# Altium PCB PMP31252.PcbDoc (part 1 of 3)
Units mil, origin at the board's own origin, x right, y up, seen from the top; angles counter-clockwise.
Board outline 4527.56 x 3188.98 mil, 6 copper layers (Top Layer, Layer 1, Layer 3, Layer 4, Layer 2, Bottom Layer), stack 32.112 mil thick; 215 components, 83 nets, 499 pads, 1248 vias.
Unrouted connection lines stored in the file: 2.
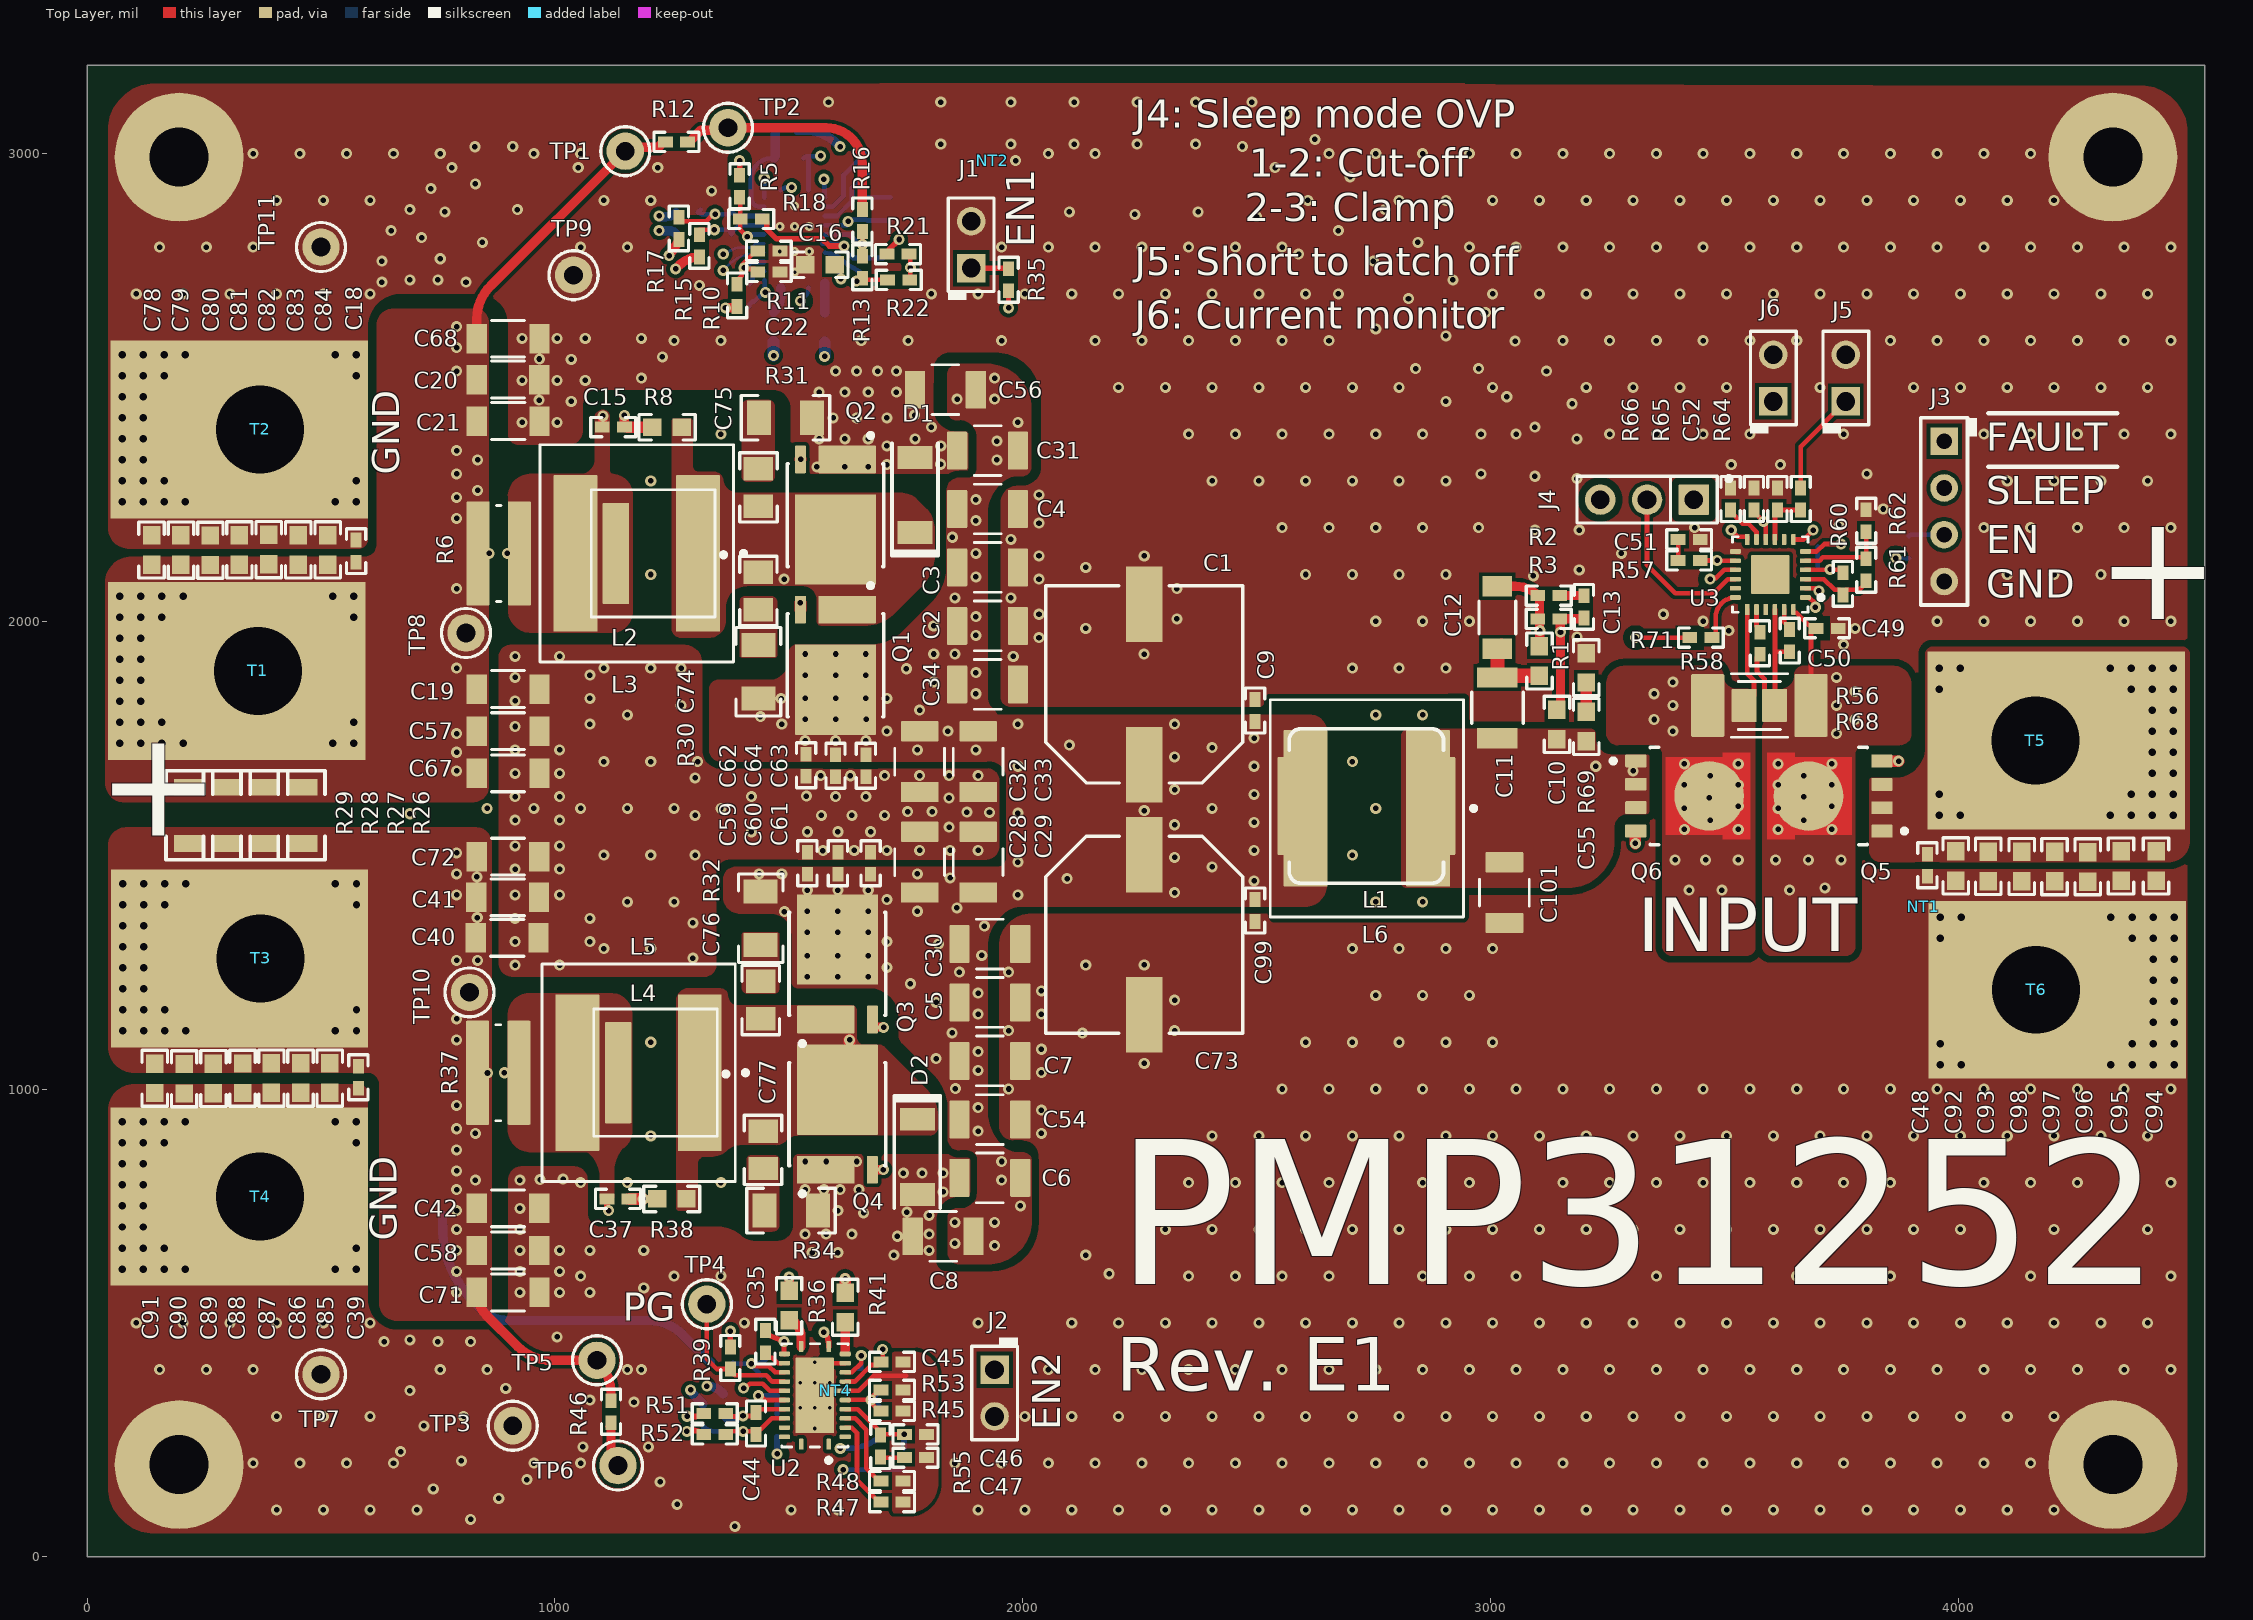
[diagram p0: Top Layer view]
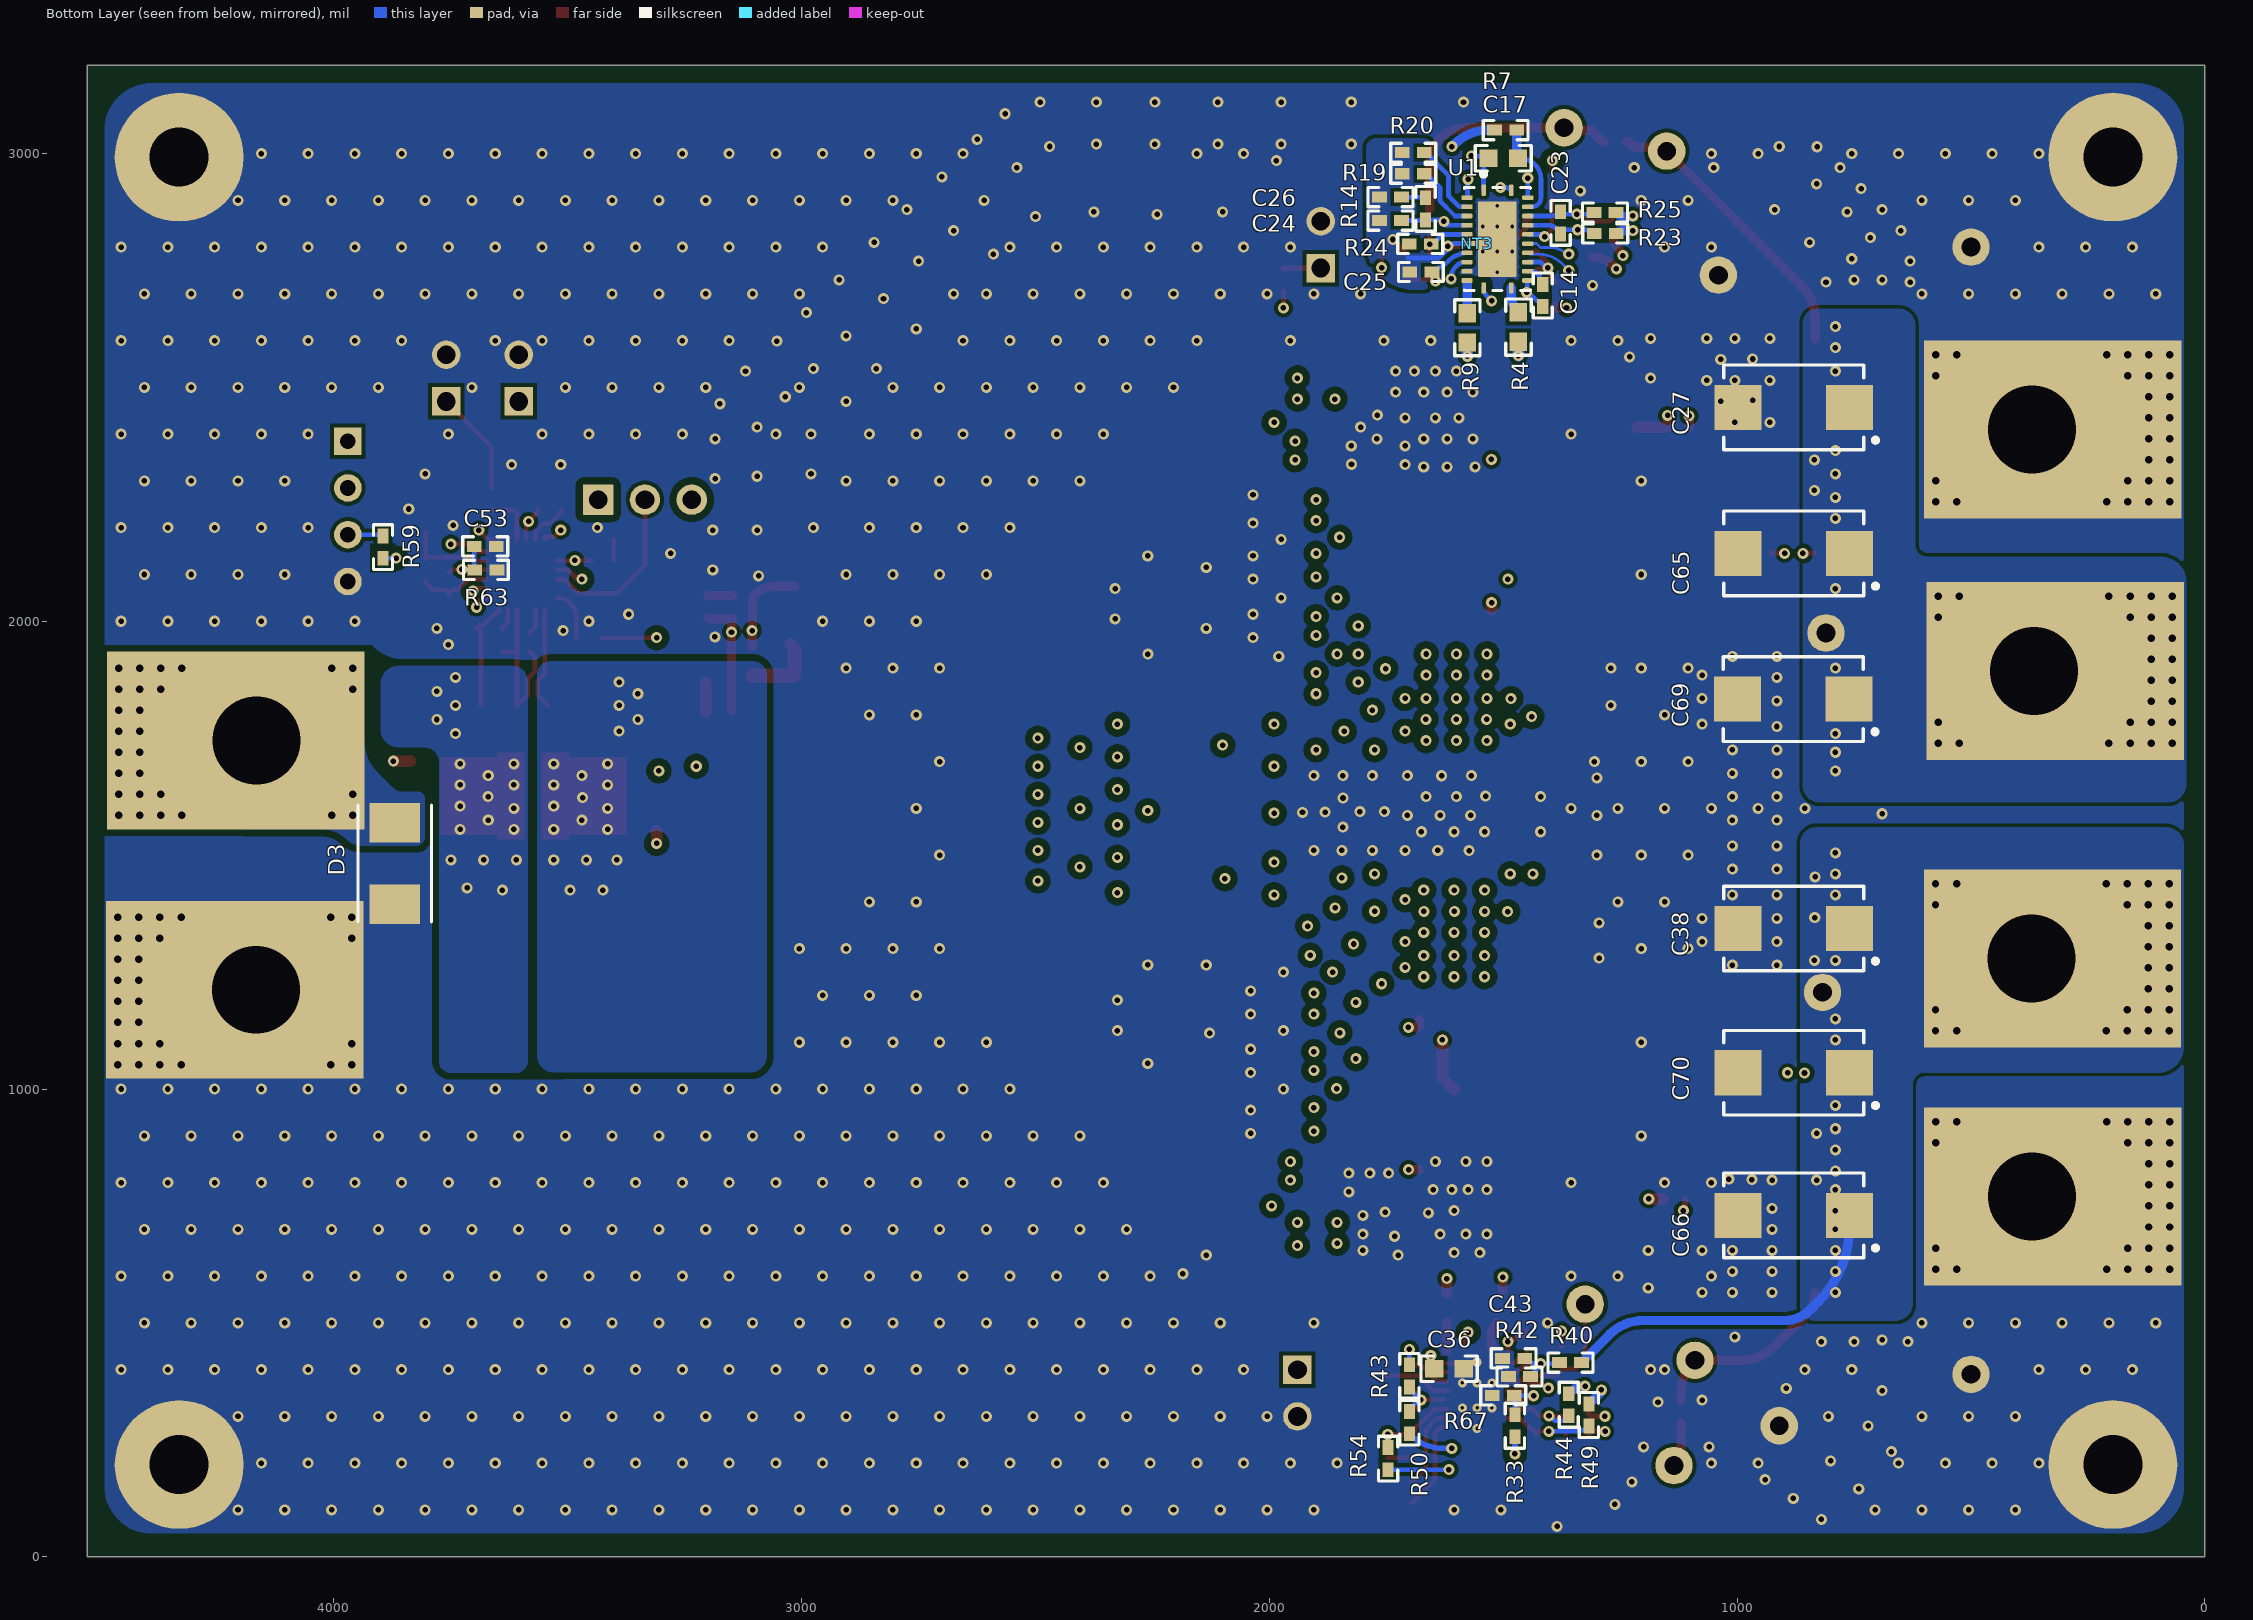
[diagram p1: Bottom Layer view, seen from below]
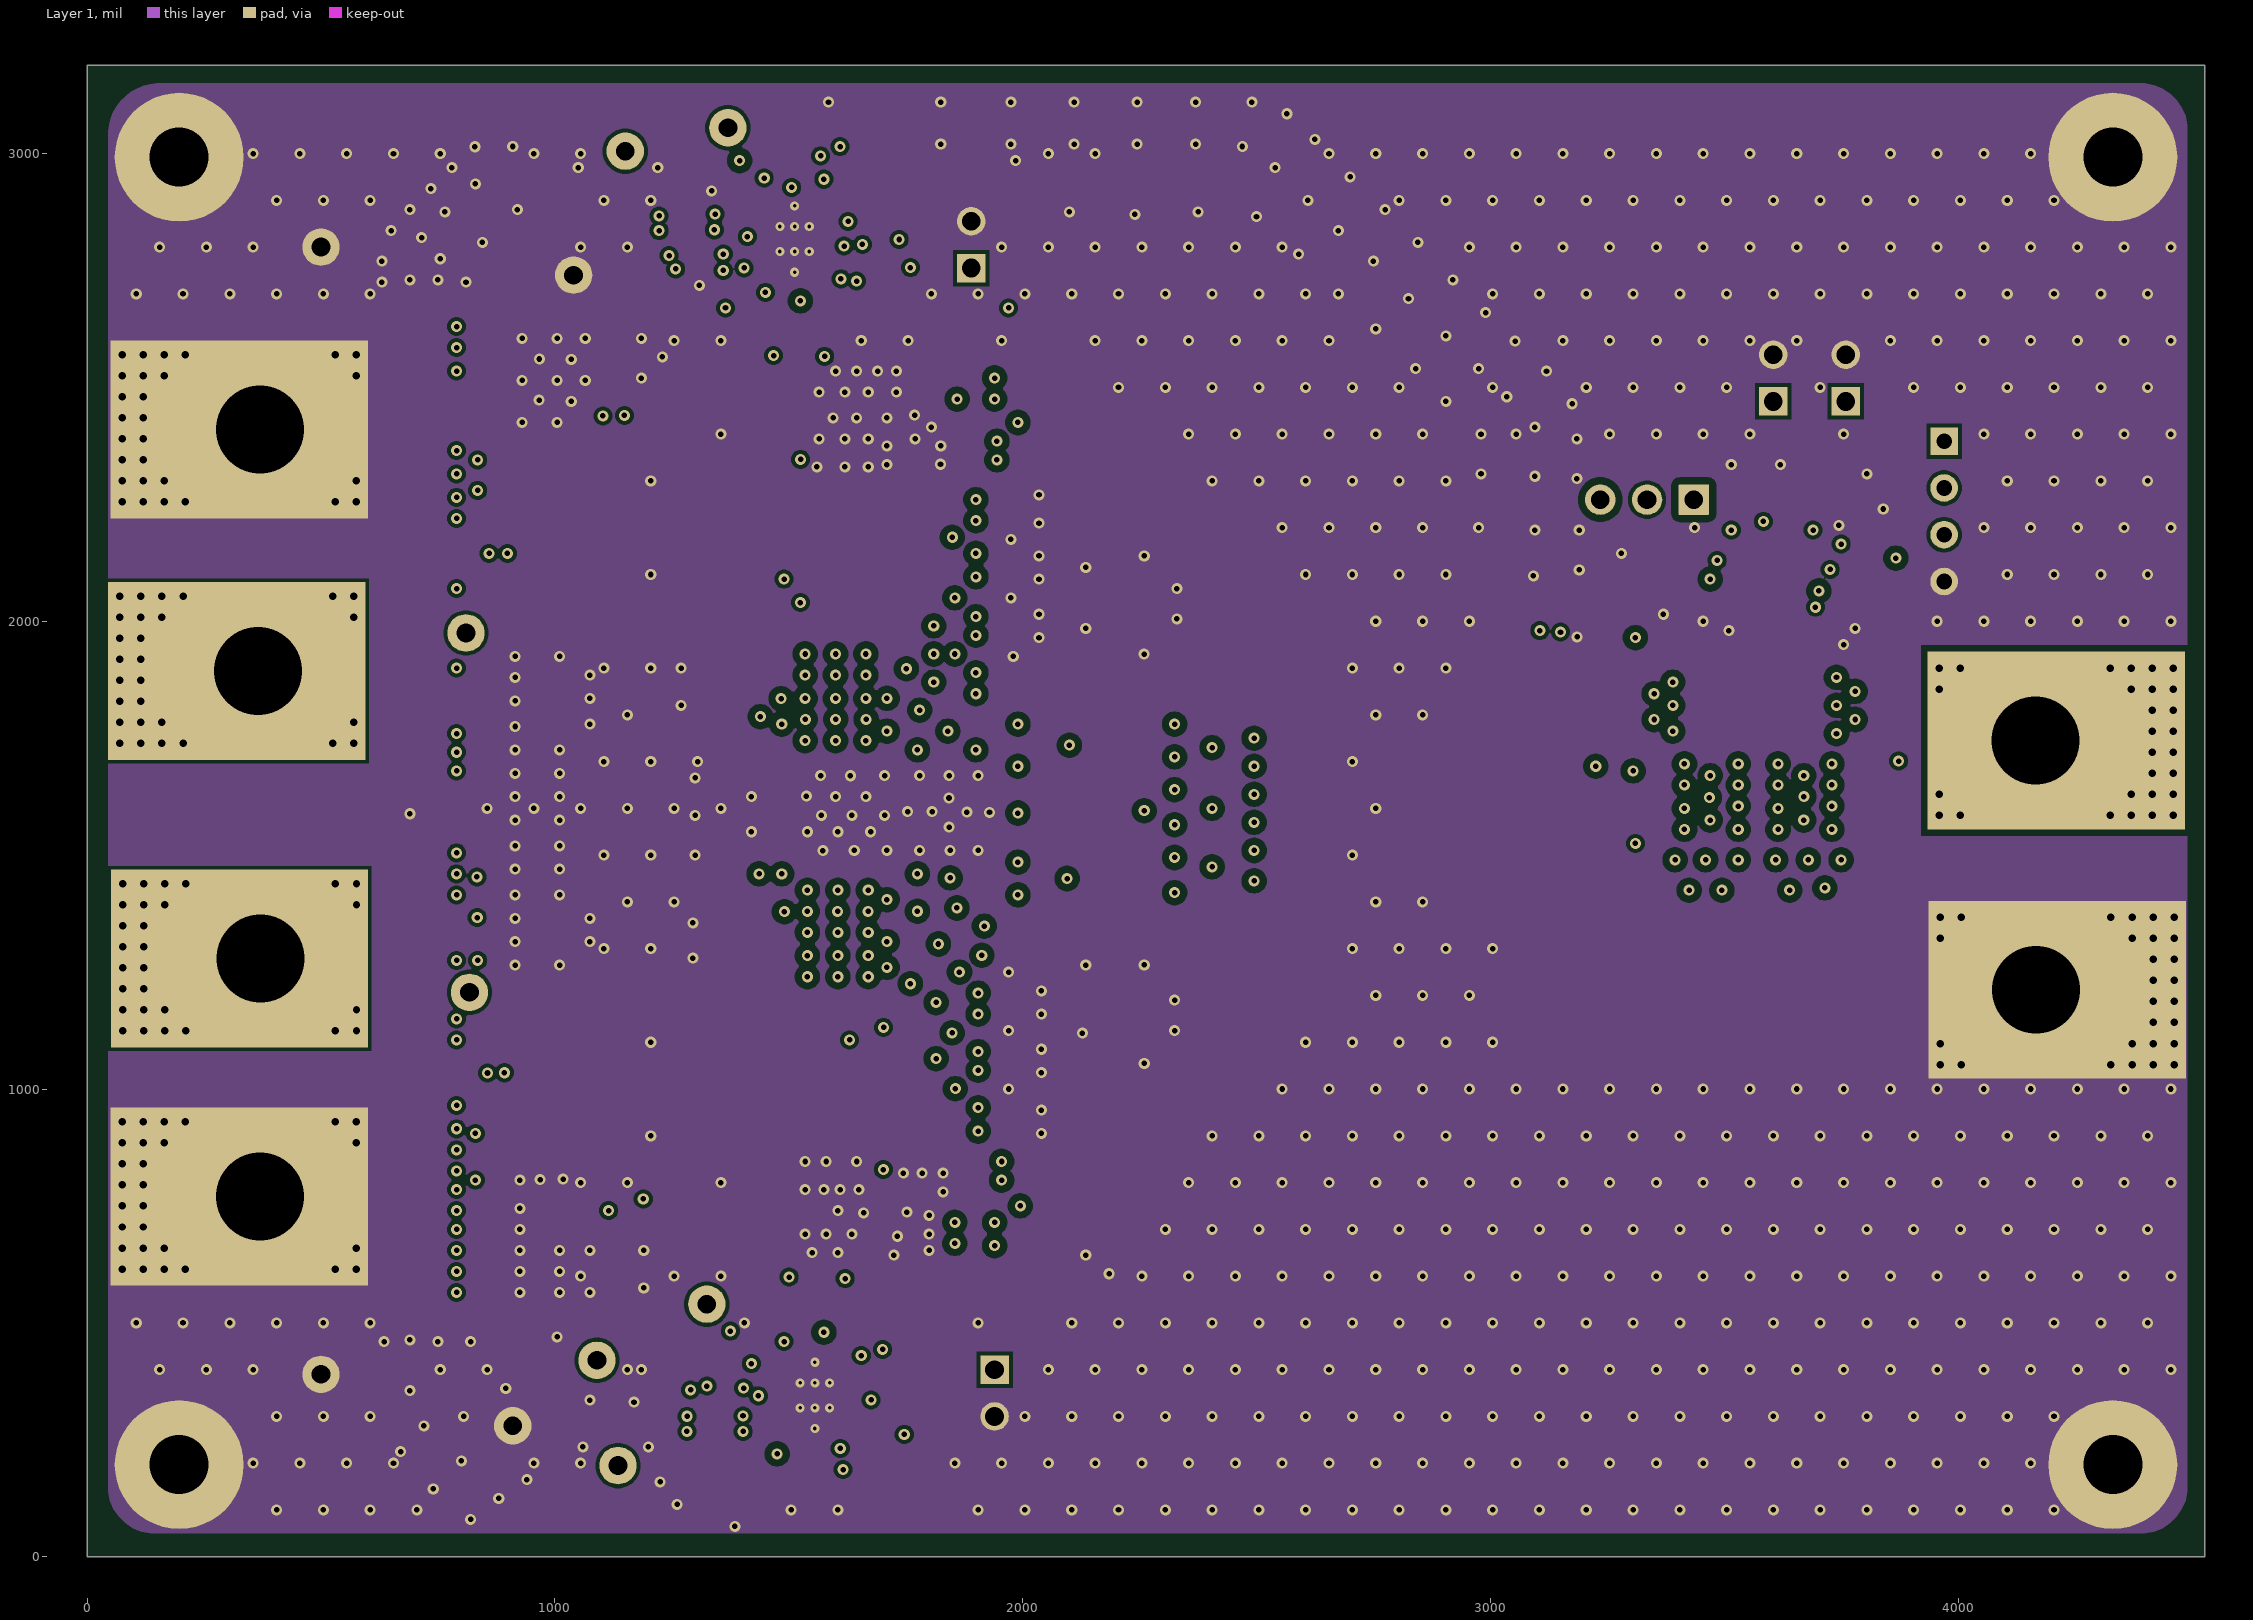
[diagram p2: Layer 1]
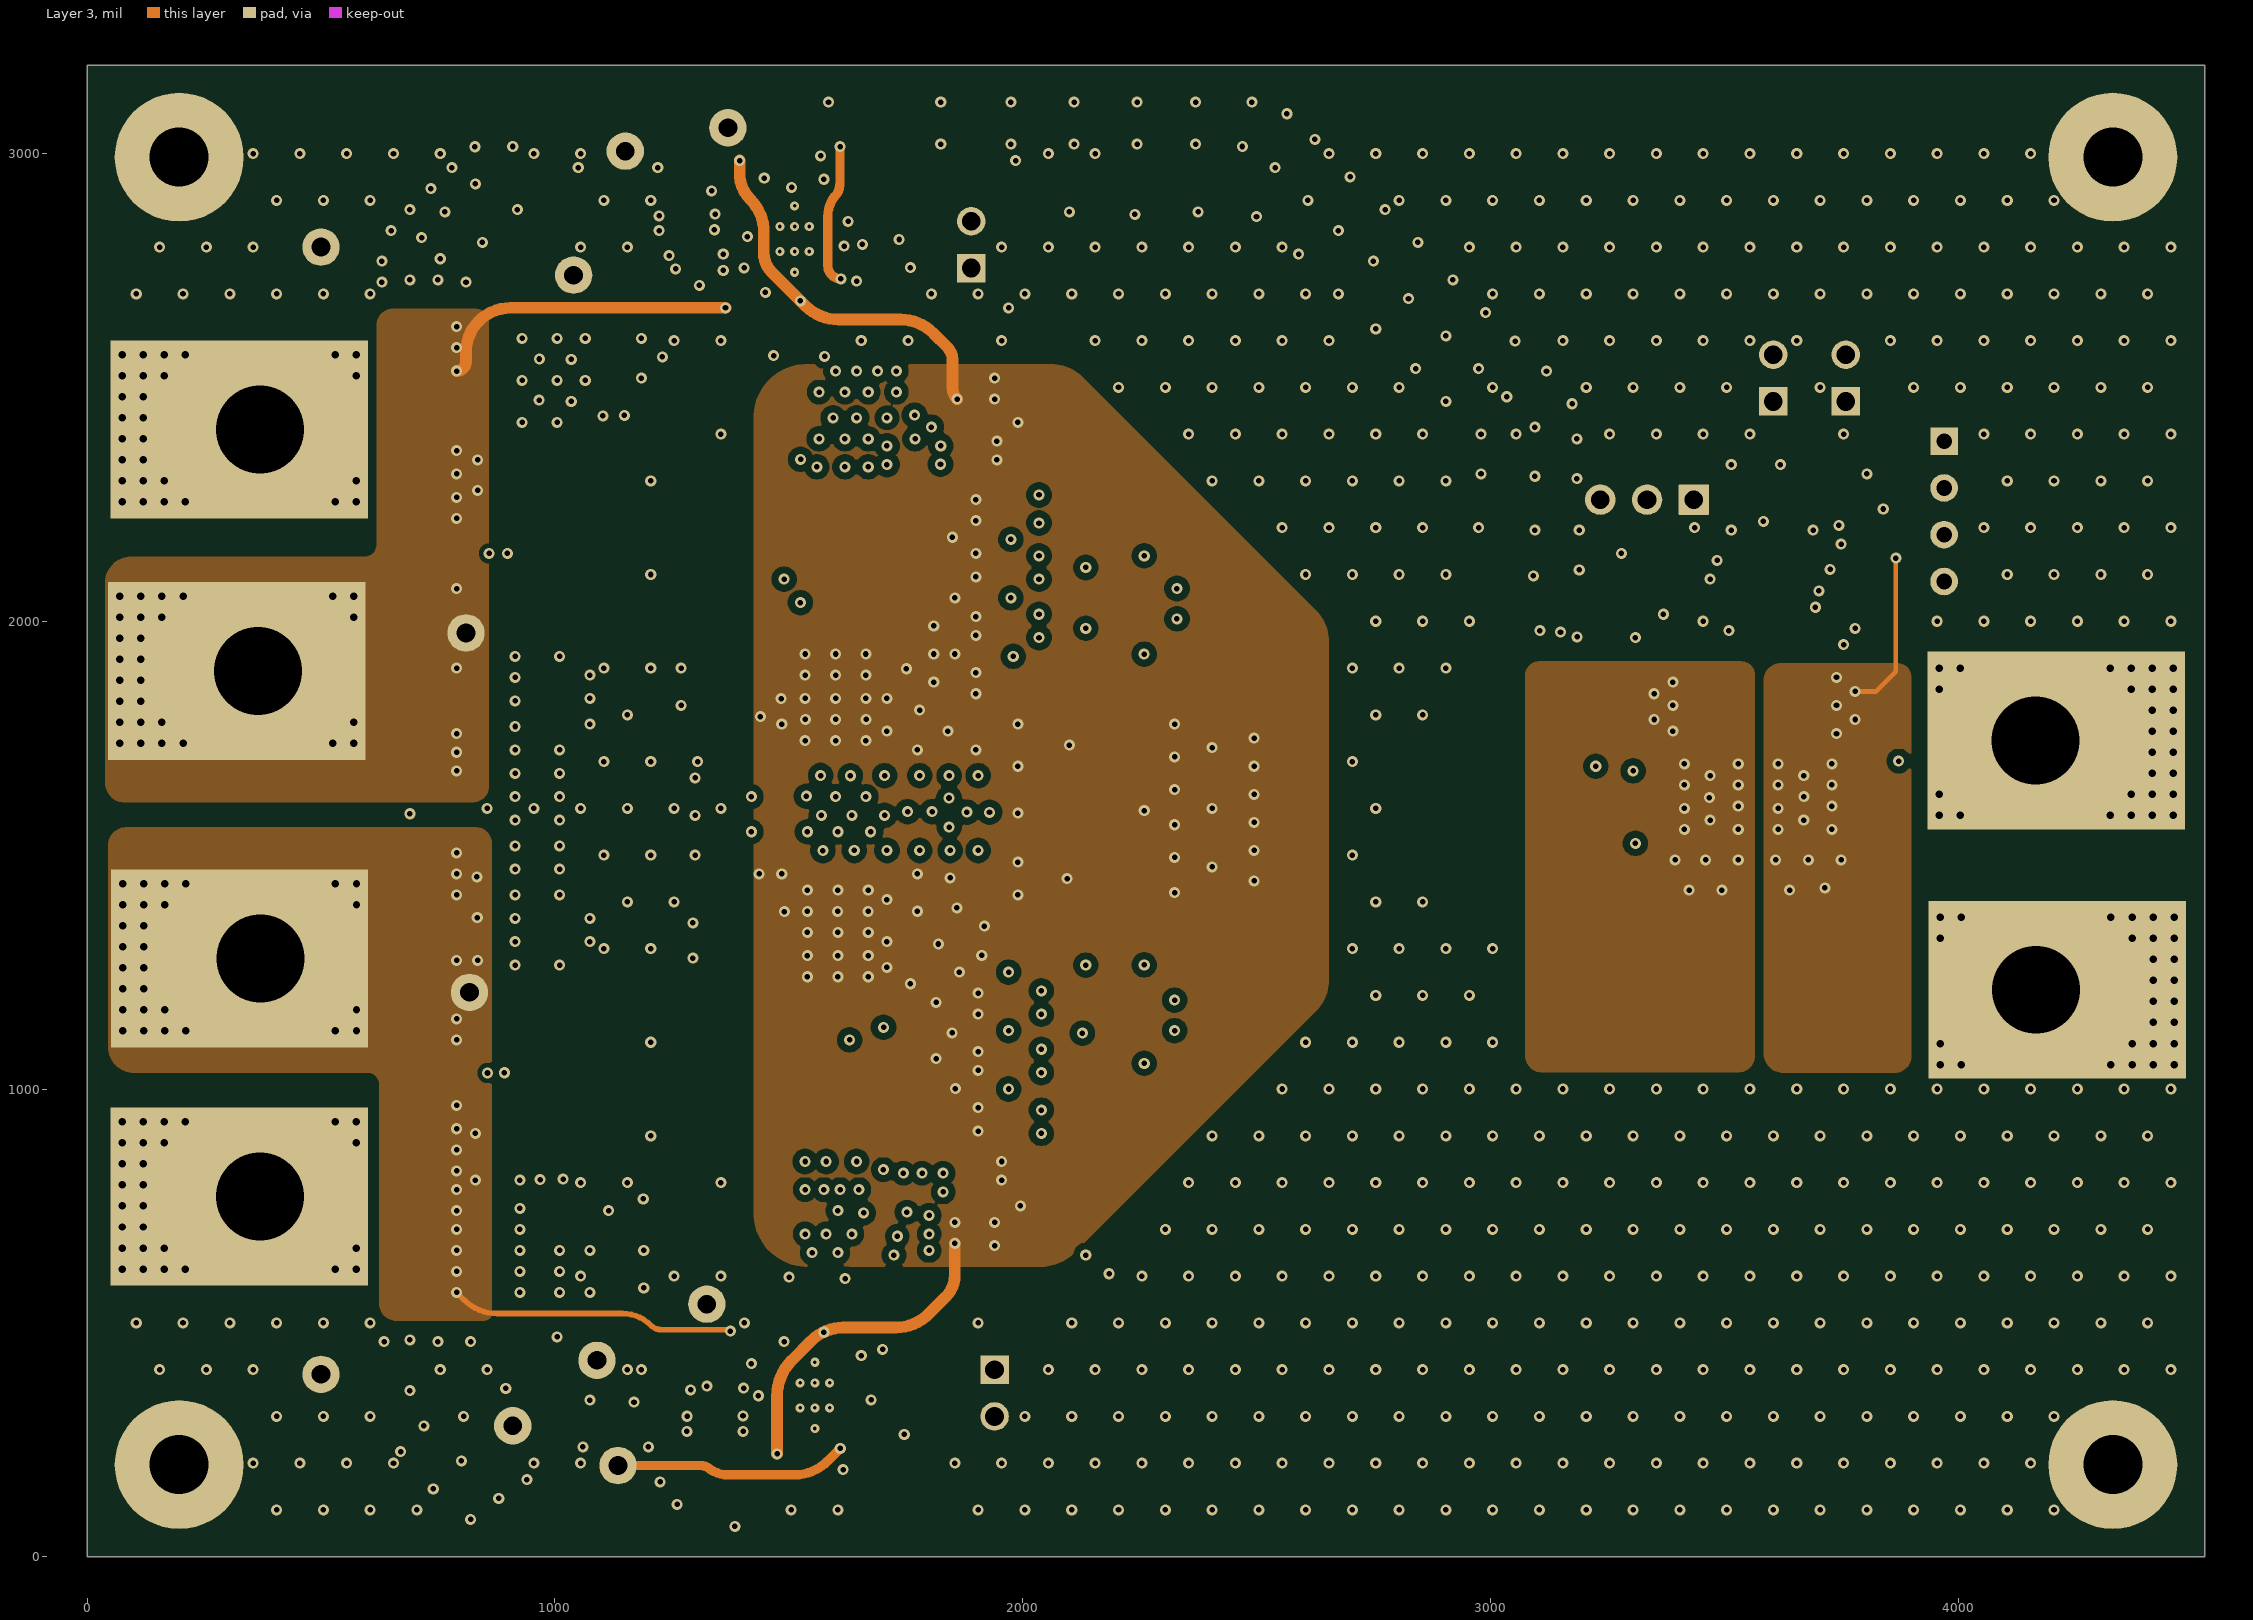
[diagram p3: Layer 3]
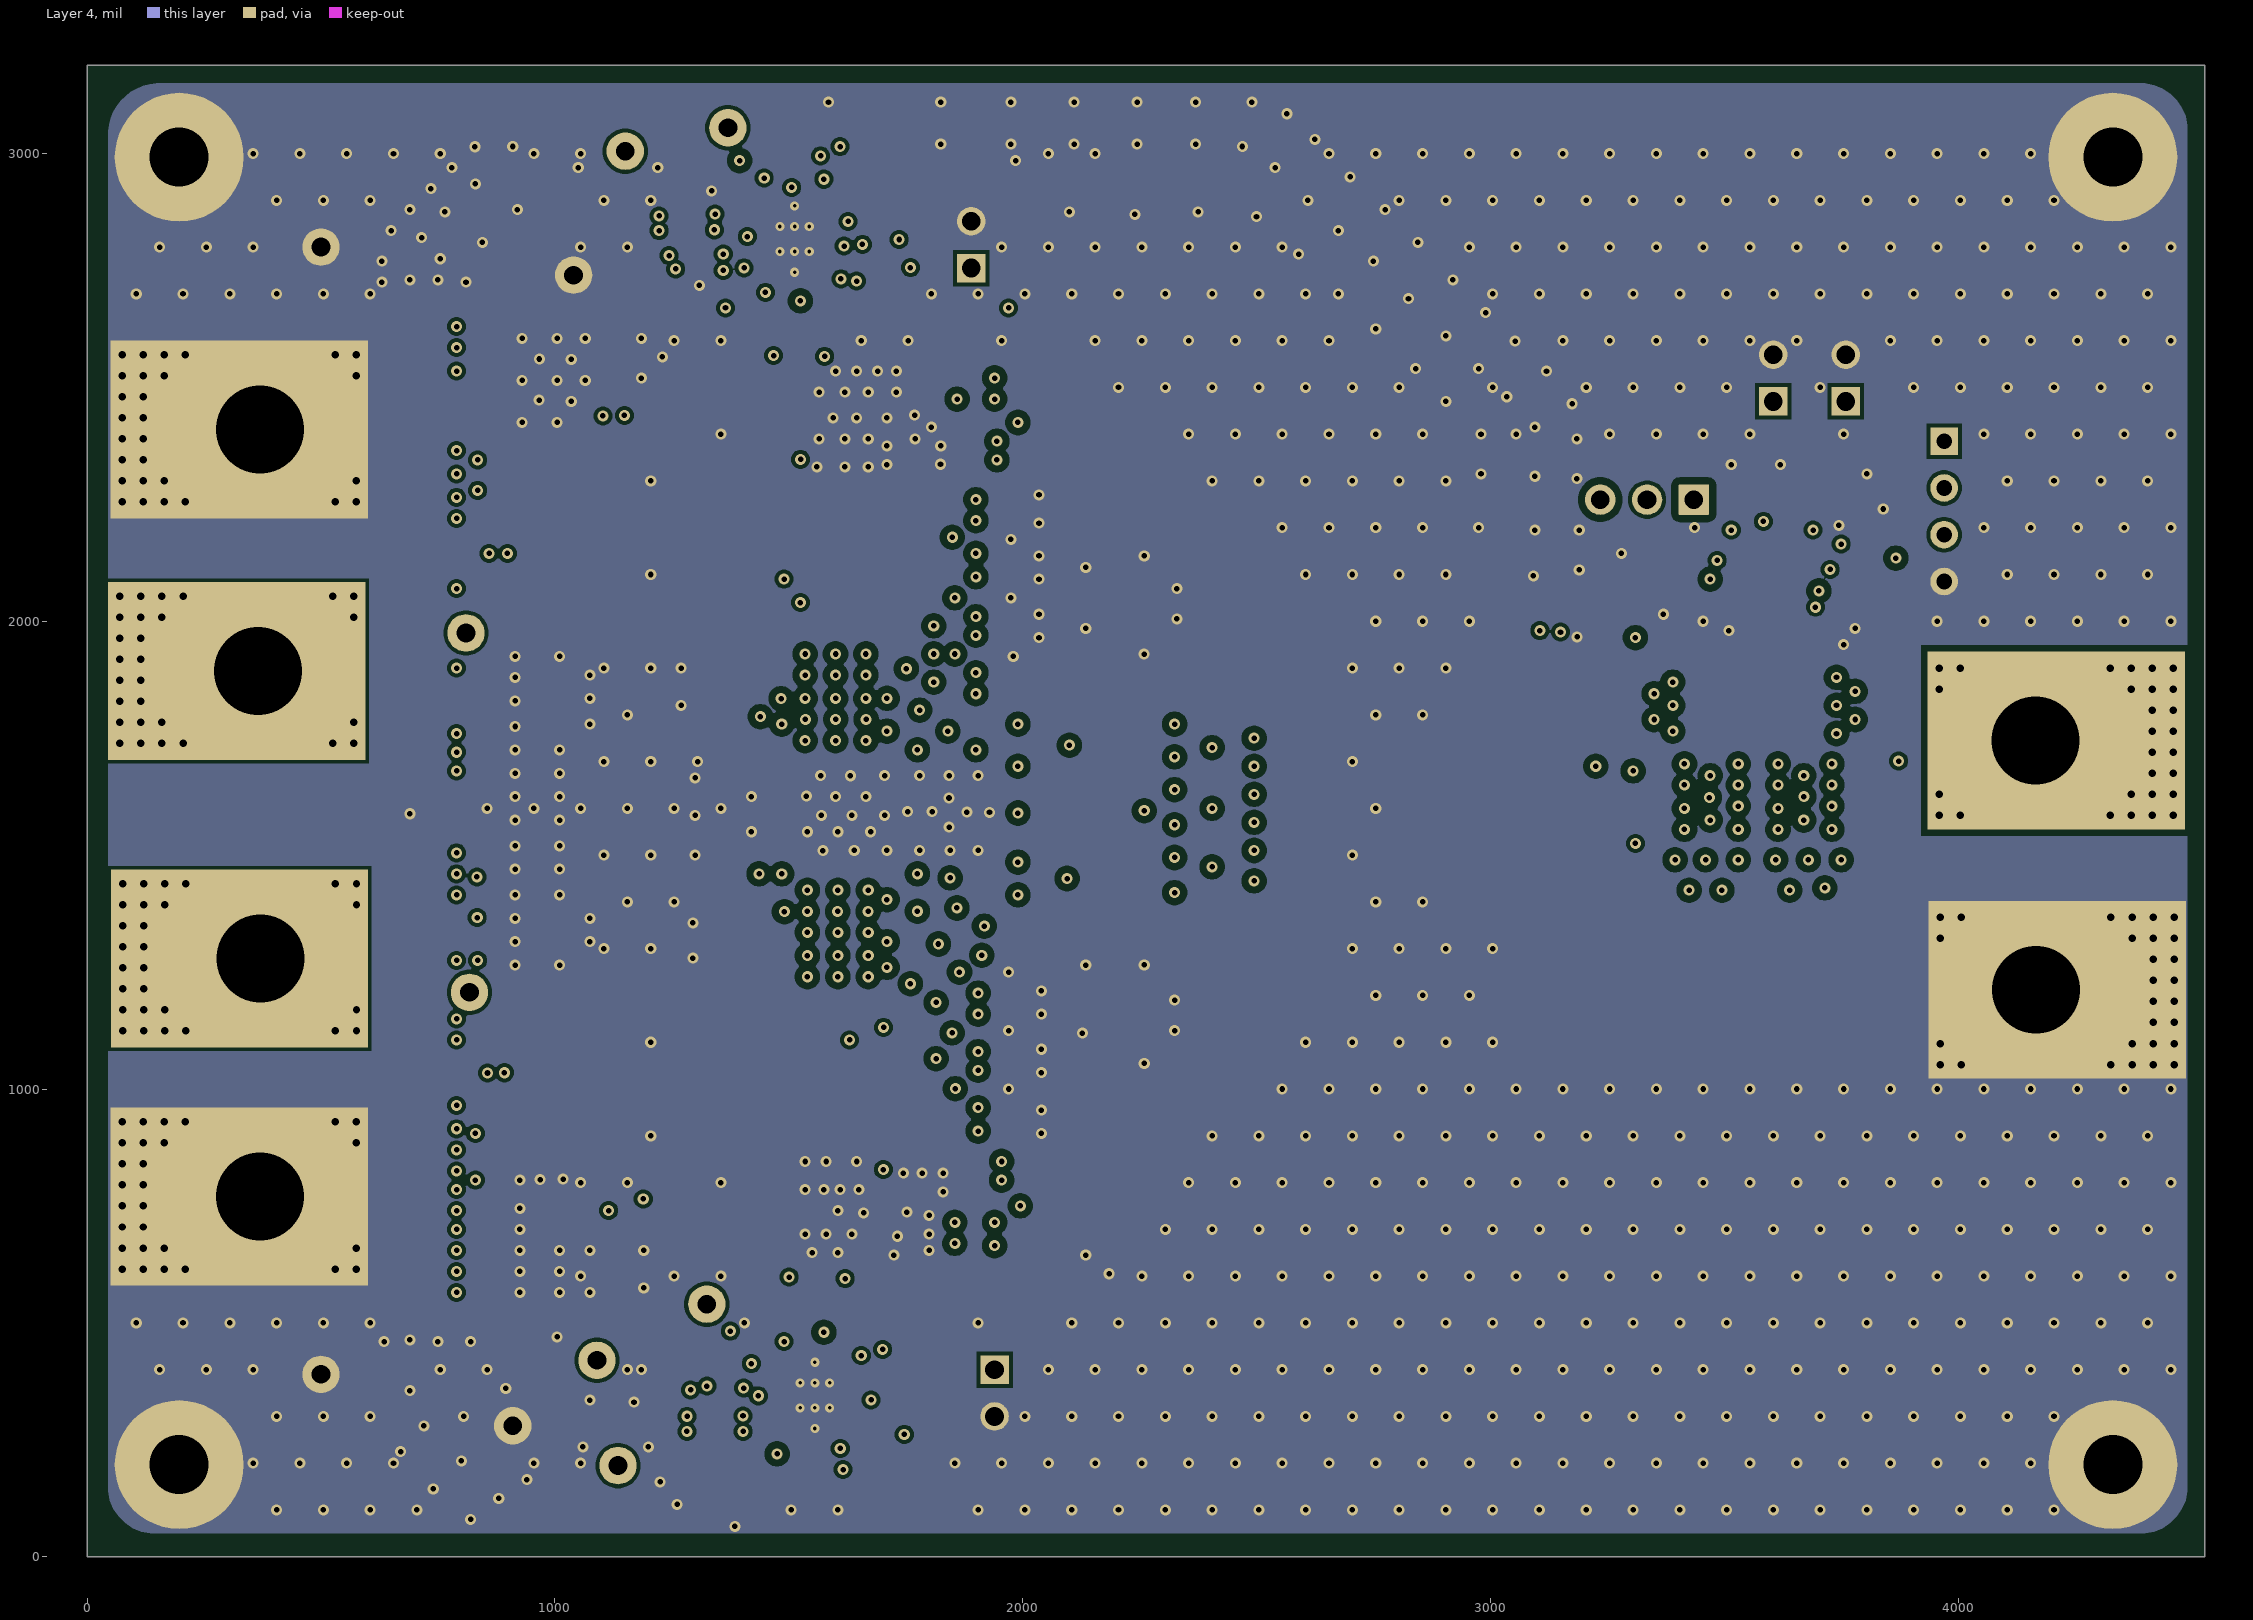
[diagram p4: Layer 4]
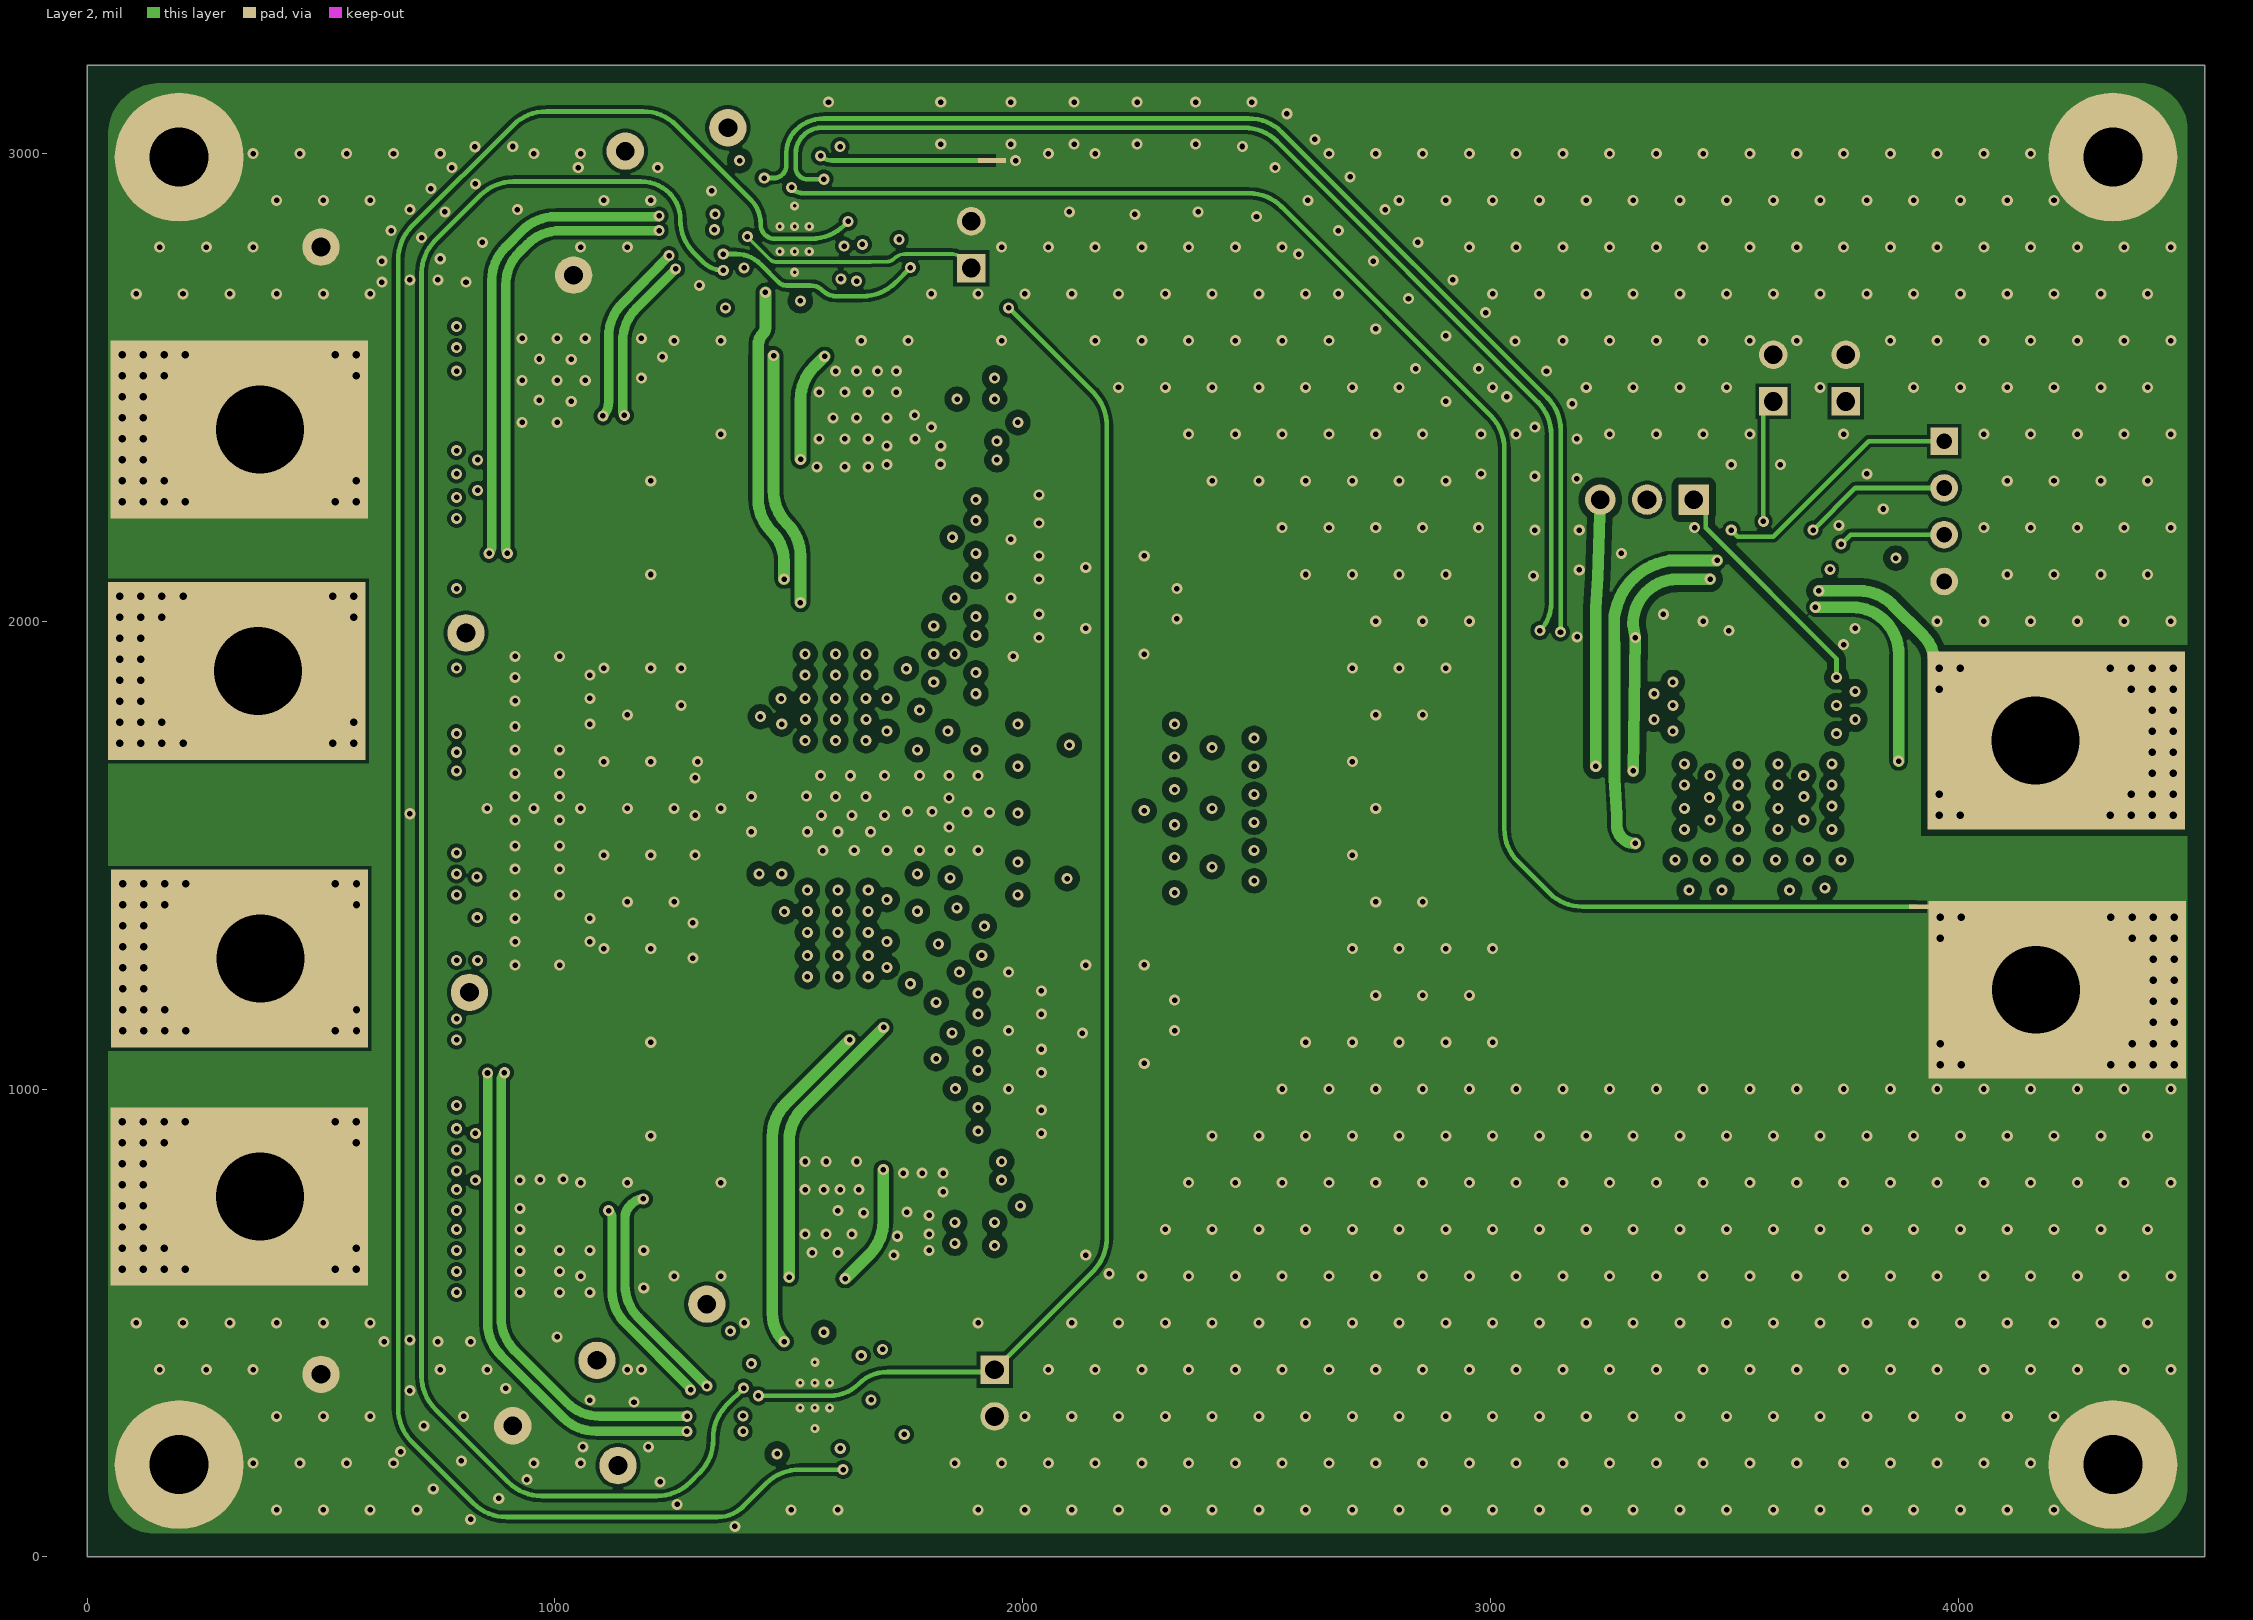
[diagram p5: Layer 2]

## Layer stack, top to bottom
Top Solder: solder mask 0.4, Solder Resist, Dk 3.5
Top Layer: signal copper 1.4
Dielectric 2: prepreg 2.8, PP-006, Dk 4.1
Layer 1: signal copper 1.378
Dielectric 4: prepreg 2.8, PP-006, Dk 4.1
Layer 3: signal copper 1.378
Dielectric 1: dielectric 12.6, FR-4, Dk 4.8
Layer 4: signal copper 1.378
Dielectric 5: prepreg 2.8, PP-006, Dk 4.1
Layer 2: signal copper 1.378
Dielectric 3: prepreg 2.8, PP-006, Dk 4.1
Bottom Layer: signal copper 1.4
Bottom Solder: solder mask 0.4, Solder Resist, Dk 3.5

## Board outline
0,0 0,3188.98 4527.56,3188.98 4527.56,0

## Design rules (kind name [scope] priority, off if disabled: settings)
Clearance Vin [InNet('Vin_FLT') OR InNet('VIN_PROT') OR InNet('NetC48_1') OR InNet('NetC49_1') OR InNet('NetQ6_5')] p1: gap=15 ignorepadtopadclearanceinfootprint=FALSE
Clearance Clearance_1 [All] p2: gap=8 ignorepadtopadclearanceinfootprint=FALSE
MinimumSolderMaskSliver [All] p1: minsoldermaskwidth=5
PolygonConnect [All] p1: connectstyle=Direct reliefconductorwidth=10 reliefentries=4 polygonreliefangle="90 Angle" airgapwidth=10
RoutingVias [All] p1: holewidth=11.81 width=23.62 viastyle="Through Hole" minholewidth=11.81 minwidth=23.62 maxholewidth=28 maxwidth=50
SilkToSolderMaskClearance [IsPad] p1: minsilkscreentomaskgap=5 clearancetoexposedcopper=TRUE
SolderMaskExpansion [All] p1: expansion=4 istentingtop=FALSE
Width [All] p1: maxlimit=50 minlimit=5 preferedwidth=10 minimp=50.000000 maximp=50.000000 favimp=50.000000
28 further rules are at their usual default settings.

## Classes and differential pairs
component class PMP31252RevA_S: C28 C29 C30 C31 C32 C33 C34 C35 C36 C37 C38 C39 C40 C41 C42 C43 C44 C45 C46 C47 C58 C62 C63 C64 C66 C70 C71 C72 C76 C77 C85 C86 C87 C88 C89 C90 C91 D2 L4 L5 NT4 Q3 Q4 R32 R34 R36 R37 R38 R39 R40 R41 R42 R43 R44 R45 R46 R47 R48 R49 R50 R51 R52 R53 R54 R55 T3 T4 TP4 TP5 TP6 TP7 U2
component class PMP31252RevA_M: C1 C2 C3 C4 C5 C6 C7 C8 C9 C10 C11 C12 C13 C14 C15 C16 C17 C18 C19 C20 C21 C22 C23 C24 C25 C26 C27 C54 C55 C56 C57 C59 C60 C61 C65 C67 C68 C69 C73 C74 C75 C78 C79 C80 C81 C82 C83 C84 C99 C101 D1 J1 J2 L1 L2 L3 L6 NT1 NT2 NT3 Q1 Q2 R1 R2 R3 R4 R5 R6 R7 R8 R9 R10 R11 R12 R13 R14 R15 R16 R17 R18 R19 R20 R21 R22 R23 R24 R25 R26 R27 R28 R29 R30 R31 R33 R35 R67 R69 T1 T2 TP1 TP2 TP3 TP8 TP9 TP10 TP11 U1
component class PMP31252RevA_Input: C48 C49 C50 C51 C52 C53 C92 C93 C94 C95 C96 C97 C98 D3 J3 J4 J5 J6 Q5 Q6 R56 R57 R58 R59 R60 R61 R62 R63 R64 R65 R66 R68 R71 T5 T6 U3

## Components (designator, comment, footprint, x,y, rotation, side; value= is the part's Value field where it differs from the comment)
C1 "EEE-FT1H331AP" SM_RADIAL_G 2260,1865 r90 top value=330uF
C2 "GCM32EC71H106KA03L" FP-GCM32EC71H106KA03L_1210-MFG 1925,1990 r180 top value=10µF
C3 "GCM32EC71H106KA03L" FP-GCM32EC71H106KA03L_1210-MFG 1925,2115 r180 top value=10µF
C4 "GCM32EC71H106KA03L" FP-GCM32EC71H106KA03L_1210-MFG 1925,2240 r180 top value=10µF
C5 "GCM32EC71H106KA03L" FP-GCM32EC71H106KA03L_1210-MFG 1930,1185 r180 top value=10µF
C6 "GCM32EC71H106KA03L" FP-GCM32EC71H106KA03L_1210-MFG 1930,810 r0 top value=10µF
C7 "GCM32EC71H106KA03L" FP-GCM32EC71H106KA03L_1210-MFG 1930,1060 r180 top value=10µF
C8 "GCM32EC71H106KA03L" FP-GCM32EC71H106KA03L_1210-MFG 1830,685 r0 top value=10µF
C9 "CGA2B3X8R1H103K050BB" 0402 2497.18,1809.13 r90 top value=0.01uF
C10 "CGA3E3X8R1H104K080AE" 0603 3142.27,1779.54 r90 top value=0.1uF
C11 "CGA6P3X7R1H475K250AB" 1210_280 3015,1815 r90 top value=4.7uF
C12 "GCM31CR71H225KA55L" 1206_180 3014.8,2008.05 r90 top value=2.2uF
C13 "GCM155R71H102KA37D" 0402 3199.93,2030.64 r270 top value=1000pF
C14 "CGA2B3X7R1E104K050BB" 0402 1415.62,2696.54 r90 bottom value=0.1uF
C15 "GCM155R71H104KE02D" 0402 1125,2415 r0 top value=0.1uF
C16 "GRM188R71A225KE15J" 0603 1566.75,2762.44 r180 top value=2.2uF
C17 "GRM188R71A225KE15J" 0603 1500,2990 r0 bottom value=2.2uF
C18 "CGA2B3X7R1E104K050BB" 0402 575,2150 r90 top value=0.1uF
C19 "GCM31CR71A226KE02L" 1206_180 900,1855 r0 top value=22uF
C20 "GCM31CR71A226KE02L" 1206_180 899.76,2516.73 r0 top value=22uF
C21 "GCM31CR71A226KE02L" 1206_180 900.18,2428.08 r0 top value=22uF
C22 "CGA2B3X7R1E104K050BB" 0402 1457.52,2746.69 r0 top value=0.1uF
C23 "CGA2B3X7R1H153K050BB" 0402 1377.52,2851.69 r90 bottom value=0.015uF
C24 "CGA2B2C0G1H151J050BA" 0402 1741.14,2856.69 r0 bottom value=150pF
C25 "CGA2B3X7R1E104K050BB" 0402 1676.14,2746.69 r0 bottom value=0.1uF
C26 "CGA2B3X7R1H153K050BB" 0402 1741.14,2906.69 r0 bottom value=0.015uF
C27 "T598D227M010ATE025" 7343-31 878.98,2457.08 r0 bottom value=220uF
C28 "GCM32EC71H106KA03L" FP-GCM32EC71H106KA03L_1210-MFG 1780,1485 r270 top value=10µF
C29 "GCM32EC71H106KA03L" FP-GCM32EC71H106KA03L_1210-MFG 1905,1485 r270 top value=10µF
C30 "GCM32EC71H106KA03L" FP-GCM32EC71H106KA03L_1210-MFG 1930,1310 r180 top value=10µF
C31 "GCM32EC71H106KA03L" FP-GCM32EC71H106KA03L_1210-MFG 1925,2365 r0 top value=10µF
C32 "GCM32EC71H106KA03L" FP-GCM32EC71H106KA03L_1210-MFG 1780,1700 r90 top value=10µF
C33 "GCM32EC71H106KA03L" FP-GCM32EC71H106KA03L_1210-MFG 1905,1700 r90 top value=10µF
C34 "GCM32EC71H106KA03L" FP-GCM32EC71H106KA03L_1210-MFG 1925,1865 r180 top value=10µF
C35 "CGA2B3X7R1E104K050BB" 0402 1450,460 r270 top value=0.1uF
C36 "GRM188R71A225KE15J" 0603 1615.87,401.77 r0 bottom value=2.2uF
C37 "GCM155R71H104KE02D" 0402 1135,765 r0 top value=0.1uF
C38 "T598D227M010ATE025" 7343-31 879.16,1343.22 r0 bottom value=220uF
C39 "CGA2B3X7R1E104K050BB" 0402 580,1025 r270 top value=0.1uF
C40 "GCM31CR71A226KE02L" 1206_180 897.98,1323.19 r0 top value=22uF
C41 "GCM31CR71A226KE02L" 1206_180 898.99,1409.78 r0 top value=22uF
C42 "GCM31CR71A226KE02L" 1206_180 899.83,744.78 r0 top value=22uF
C43 "CGA2B3X7R1E104K050BB" 0402 1477.83,424.06 r0 bottom value=0.1uF
C44 "CGA2B3X7R1H153K050BB" 0402 1430,285 r270 top value=0.015uF
C45 "CGA2B3X7R1E104K050BB" 0402 1720.87,416.77 r0 top value=0.1uF
C46 "CGA2B2C0G1H151J050BA" 0402 1770.87,261.77 r0 top value=150pF
C47 "CGA2B3X7R1H153K050BB" 0402 1770.87,211.77 r0 top value=0.015uF
C48 "CGA2B3X7R1H104K050BD" 0402 3934.34,1478.53 r270 top value=0.1uF
C49 "CGA2B3X7R1H104K050BD" 0402 3720,1985 r0 top value=0.1uF
C50 "CGA2B3X7R1H104K050BD" 0402 3640,1958.62 r90 top value=0.1uF
C51 "CGA2B3X8R1H103K050BB" 0402 3425,2175 r0 top value=0.01uF
C52 "CGA2B3X8R1H103K050BB" 0402 3613.5,2261.38 r90 top value=0.01uF
C53 "CGA2B3X8R1H103K050BB" 0402 3676.38,2160 r180 bottom value=0.01uF
C54 "GCM32EC71H106KA03L" FP-GCM32EC71H106KA03L_1210-MFG 1930,934.76 r180 top value=10µF
C55 "CGA3E3X8R1H104K080AE" 0603 3205,1775 r90 top value=0.1uF
C56 "GCM32EC71H106KA03L" FP-GCM32EC71H106KA03L_1210-MFG 1835,2495 r0 top value=10µF
C57 "GCM31CR71A226KE02L" 1206_180 900,1765 r0 top value=22uF
C58 "GCM31CR71A226KE02L" 1206_180 899.83,654.78 r0 top value=22uF
C59 "CGA2B3X7R1E104K050BB" 0402 1539.95,1482.66 r90 top value=0.1uF
C60 "CGA2B3X7R1E104K050BB" 0402 1604.95,1482.66 r90 top value=0.1uF
C61 "CGA2B3X7R1E104K050BB" 0402 1674.95,1482.66 r90 top value=0.1uF
C62 "CGA2B3X7R1E104K050BB" 0402 1537.06,1692.06 r270 top value=0.1uF
C63 "CGA2B3X7R1E104K050BB" 0402 1664.96,1690.94 r270 top value=0.1uF
C64 "CGA2B3X7R1E104K050BB" 0402 1599.96,1690.94 r270 top value=0.1uF
C65 "T598D227M010ATE025" 7343-31 878.98,2145 r0 bottom value=220uF
C66 "T598D227M010ATE025" 7343-31 878.98,729.85 r0 bottom value=220uF
C67 "GCM31CR71A226KE02L" 1206_180 900,1675 r0 top value=22uF
C68 "GCM31CR71A226KE02L" 1206_180 899.98,2603.97 r0 top value=22uF
C69 "T598D227M010ATE025" 7343-31 880,1833.65 r0 bottom value=220uF
C70 "T598D227M010ATE025" 7343-31 878.98,1034.78 r0 bottom value=220uF
C71 "GCM31CR71A226KE02L" 1206_180 900,565 r0 top value=22uF
C72 "GCM31CR71A226KE02L" 1206_180 899.68,1496.71 r0 top value=22uF
C73 "EEE-FT1H331AP" SM_RADIAL_G 2260,1330 r270 top value=330uF
C74 "GRM21BR72A103KA01L" 0805_HV 1435,2065 r90 top value=0.01uF
C75 "GRM21BR72A103KA01L" 0805_HV 1435.26,2286.16 r90 top value=0.01uF
C76 "GRM21BR72A103KA01L" 0805_HV 1440,1190 r270 top value=0.01uF
C77 "GRM21BR72A103KA01L" 0805_HV 1445,870 r270 top value=0.01uF
C78 "CGA3E3X8R1H104K080AE" 0603 137.9,2152.29 r90 top value=0.1uF
C79 "CGA3E3X8R1H104K080AE" 0603 200.62,2152 r90 top value=0.1uF
C80 "CGA3E3X8R1H104K080AE" 0603 263.5,2151.8 r90 top value=0.1uF
C81 "CGA3E3X8R1H104K080AE" 0603 325.52,2152.53 r90 top value=0.1uF
C82 "CGA3E3X8R1H104K080AE" 0603 388.27,2153.13 r90 top value=0.1uF
C83 "CGA3E3X8R1H104K080AE" 0603 451.19,2152.68 r90 top value=0.1uF
C84 "CGA3E3X8R1H104K080AE" 0603 514.46,2152.68 r90 top value=0.1uF
C85 "CGA3E3X8R1H104K080AE" 0603 518.72,1023.19 r270 top value=0.1uF
C86 "CGA3E3X8R1H104K080AE" 0603 456.29,1023.19 r270 top value=0.1uF
C87 "CGA3E3X8R1H104K080AE" 0603 393.85,1023.42 r270 top value=0.1uF
C88 "CGA3E3X8R1H104K080AE" 0603 332.34,1022.96 r270 top value=0.1uF
C89 "CGA3E3X8R1H104K080AE" 0603 270.06,1022.43 r270 top value=0.1uF
C90 "CGA3E3X8R1H104K080AE" 0603 207.37,1021.97 r270 top value=0.1uF
C91 "CGA3E3X8R1H104K080AE" 0603 144.69,1022.9 r270 top value=0.1uF
C92 "CGA3E3X8R1H104K080AE" 0603 3994.99,1476.93 r270 top value=0.1uF
C93 "CGA3E3X8R1H104K080AE" 0603 4064.36,1475.91 r270 top value=0.1uF
C94 "CGA3E3X8R1H104K080AE" 0603 4423.07,1476.78 r270 top value=0.1uF
C95 "CGA3E3X8R1H104K080AE" 0603 4348.42,1476.78 r270 top value=0.1uF
C96 "CGA3E3X8R1H104K080AE" 0603 4277.02,1475.02 r270 top value=0.1uF
C97 "CGA3E3X8R1H104K080AE" 0603 4206.13,1475.56 r270 top value=0.1uF
C98 "CGA3E3X8R1H104K080AE" 0603 4136,1475.64 r270 top value=0.1uF
C99 "CGA2B3X8R1H103K050BB" 0402 2496.89,1381.69 r270 top value=0.01uF
C101 "GCM32EC71H106KA03L" FP-GCM32EC71H106KA03L_1210-MFG 3030,1420 r270 top value=10µF
D1 "FSV340AF" SMAF 1770,2270 r90 top value=40V
D2 "FSV340AF" SMAF 1775,855 r270 top value=40V
D3 "SMBJ33CA-13-F" SMB-Bi 3870,1482.01 r90 bottom value=33V
J1 "HMTSW-102-07-G-S-240" SAMTEC_HMTSW-102-07-G-S-240 1890,2805 r90 top
J2 "HMTSW-102-07-G-S-240" SAMTEC_HMTSW-102-07-G-S-240 1940,350 r270 top
J3 "800-10-004-10-001000" Mill-Max_800-10-004-10-001000 3970,2235 r270 top
J4 "HTSW-103-07-G-S" Samtec_HTSW-103-07-G-S 3335,2260 r180 top
J5 "HMTSW-102-07-G-S-240" SAMTEC_HMTSW-102-07-G-S-240 3760,2520 r90 top
J6 "HMTSW-102-07-G-S-240" SAMTEC_HMTSW-102-07-G-S-240 3605,2520 r90 top
L1 "IHLP3232DZERR47M5A" IHLP-3232DZ 2735,1605 r180 top value=470nH
L2 "XGL6060-182MEC" FP-XGL6060-472MEC_SMT2_6MM51_6MM71-MFG 1210,2145 r180 top value=4.7uH
L3 "XGL1010-801MEC" FP-XGL1060-332MEC_SMT2_10MM0_11MM3-MFG 1175,2145 r180 top value=3.3uH
L4 "XGL6060-182MEC" FP-XGL6060-472MEC_SMT2_6MM51_6MM71-MFG 1215,1035 r180 top value=4.7uH
L5 "XGL1010-801MEC" FP-XGL1060-332MEC_SMT2_10MM0_11MM3-MFG 1178.99,1034.78 r180 top value=3.3uH
L6 "XGL1010-801MEC" FP-XGL1060-332MEC_SMT2_10MM0_11MM3-MFG 2735.91,1600 r180 top value=3.3uH
NT1 "Net-Tie" Net-Tie_10milWide_30milLong#1 3925,1390 r0 top net-tie
NT2 "Net-Tie" Net-Tie_10milWide_30milLong#1 1935,2985 r0 top net-tie
NT3 "Net-Tie" Net-Tie_10milWide_30milLong#2 1556.75,2807.44 r180 bottom net-tie
NT4 "Net-Tie" Net-Tie_10milWide_30milLong#2 1599.76,355.09 r180 top net-tie
Q1 "IAUC100N04S6L014" FP-IAUC120N04S6N009ATMA1_TDSON8-MFG 1599.96,1905.94 r180 top
Q2 "IAUC120N04S6L005" FP-IAUC120N04S6N009ATMA1_TDSON8-MFG 1599.96,2227.05 r180 top
Q3 "IAUC100N04S6L014" FP-IAUC120N04S6N009ATMA1_TDSON8-MFG 1603.94,1267.44 r0 top
Q4 "IAUC120N04S6L005" FP-IAUC120N04S6N009ATMA1_TDSON8-MFG 1603.94,946.34 r0 top
Q5 "NVMFWS0D5N04XM" FP-BUK9J0R9-40H_SOT1023-MFG 3713.52,1626.27 r90 top
Q6 "NVMFWS0D5N04XM" FP-BUK9J0R9-40H_SOT1023-MFG 3434.46,1626.61 r270 top
R1 "CRCW060310R0FKEA" 0603 3105,1915 r270 top value=10.0
R2 "ERA-2APB102X" 0402 3125,2055 r180 top value=1.00k
R3 "ERJ-2RKF4992X" 0402 3125,2005 r180 top value=49.9k
R4 "CRCW06032R21FKEA" 0603 1467.56,2628.94 r270 bottom value=2.21
R5 "CRCW0402100KFKED" 0402 1395,2930 r90 top value=100k
R6 "WSL10203L000FEA" FP-WSL10203L000FEA_1020-MFG 880,2145 r180 top value=3m
R7 "CRCW04023R00JNED" 0402 1495,3050 r180 bottom value=3.0
R8 "CRCW06030000Z0EA" 0603 1240,2415 r180 top value=0
R9 "CRCW06030000Z0EA" 0603 1576.75,2627.44 r270 bottom value=0
R10 "ERJ-2GE0R00X" 0402 1389.53,2696.68 r270 top value=0
R11 "ERJ-2GE0R00X" 0402 1457.52,2791.69 r180 top value=0
R12 "ERJ-2RKF49R9X" 0402 1260,3025 r180 top value=49.9
R13 "CRCW040224K9FKED" 0402 1657.52,2756.69 r270 top value=24.9k
R14 "CRCW040224K0JNED" 0402 1666.14,2881.69 r270 bottom value=24k
R15 "ERJ-2GE0R00X" 0402 1309,2802.5 r270 top value=0
R16 "CRCW040247K5FKED" 0402 1657.52,2856.69 r90 top value=47.5k
R17 "ERJ-2GE0R00X" 0402 1265,2840 r270 top value=0
R18 "CRCW040211K8FKED" 0402 1420,2860 r180 top value=11.8k
R19 "ERJ-2RKF4992X" 0402 1692.52,2956.69 r180 bottom value=49.9k
R20 "CRCW040271K5FKED" 0402 1692.52,3001.69 r180 bottom value=71.5k
R21 "ERJ-2GE0R00X" 0402 1733.62,2785 r0 top value=0
R22 "ERJ-2GE0R00X" 0402 1735,2730 r0 top value=0
R23 "ERJ-2RKF49R9X" 0402 1282.07,2829.04 r180 bottom value=49.9
R24 "CRCW04029K09FKED" 0402 1677.52,2806.69 r0 bottom value=9.09k
R25 "ERJ-2GE0R00X" 0402 1282.56,2873.94 r180 bottom value=0
R26 "D55342E07B000ATTR" RM1206 458.76,1585.19 r90 top value=0
R27 "D55342E07B000ATTR" RM1206 378.76,1585.19 r90 top value=0
R28 "D55342E07B000ATTR" RM1206 298.76,1585.19 r90 top value=0
R29 "D55342E07B000ATTR" RM1206 218.76,1585.19 r90 top value=0
R30 "RC1206FR-07110RL" 1206 1435,1892.09 r270 top value=110
R31 "RC1206FR-07110RL" 1206 1493.04,2435.12 r180 top value=110
R32 "RC1206FR-07110RL" 1206 1440,1365 r90 top value=110
R33 "CRCW0402100KFKED" 0402 1475,280 r270 bottom value=100k
R34 "RC1206FR-07110RL" 1206 1505,740 r180 top value=110
R35 "ERJ-2GE0R00X" 0402 1970,2730 r270 top value=0
R36 "CRCW06032R21FKEA" 0603 1500.87,536.77 r90 top value=2.21
R37 "WSL10203L000FEA" FP-WSL10203L000FEA_1020-MFG 878.98,1034.78 r180 top value=3m
R38 "CRCW06030000Z0EA" 0603 1250,765 r180 top value=0
R39 "RMCF0402FT100K" 0402 1375,425 r90 top value=100k
R40 "ERJ-2GE0R00X" 0402 1356.38,415 r180 bottom value=0
R41 "CRCW06030000Z0EA" 0603 1620.87,533.27 r90 top value=0
R42 "ERJ-2GE0R00X" 0402 1465.4,385.39 r180 bottom value=0
R43 "ERJ-2GE0R00X" 0402 1700.87,386.77 r270 bottom value=0
R44 "ERJ-2GE0R00X" 0402 1360,325 r90 bottom value=0
R45 "ERJ-2GE0R00X" 0402 1720.87,311.77 r180 top value=0
R46 "ERJ-2RKF49R9X" 0402 1120,310 r90 top value=49.9
R47 "CRCW040290K9FKED" 0402 1720.87,116.77 r180 top value=90.9k
R48 "ERJ-2RKF4992X" 0402 1720.87,161.77 r180 top value=49.9k
R49 "ERJ-2GE0R00X" 0402 1316.75,303.1 r90 bottom value=0
R50 "CRCW040224K9FKED" 0402 1700.87,286.77 r90 bottom value=24.9k
R51 "ERJ-2RKF49R9X" 0402 1341.77,306.39 r180 top value=49.9
R52 "ERJ-2GE0R00X" 0402 1341.63,261.77 r180 top value=0
R53 "CRCW040224K9FKED" 0402 1720.69,356.71 r0 top value=24.9k
R54 "ERJ-2GE0R00X" 0402 1746.32,209.9 r90 bottom value=0
R55 "ERJ-2RKF2401X" 0402 1695.87,236.77 r90 top value=2.40k
R56 "CSSH0805FTL500" FP-CSSH0805FTL500_0805-MFG 3575,1820 r180 top value=500µ
R57 "RMCF0402JT100R" 0402 3425,2130 r0 top value=100
R58 "ERJ-2RKF49R9X" 0402 3576.18,1952.97 r270 top value=49.9
R59 "RMCF0402FT100K" 0402 3895,2158.62 r270 bottom value=100k
R60 "RMCF0402FT100K" 0402 3753.5,2080 r270 top value=100k
R61 "RMCF0402FT100K" 0402 3803.5,2110 r270 top value=100k
R62 "CRCW04021K65FKED" 0402 3803.5,2215 r270 top value=1.65k
R63 "CRCW040211K5FKED" 0402 3675,2110 r0 bottom value=11.5k
R64 "CRCW0402100KFKED" 0402 3663.5,2261.38 r270 top value=100k
R65 "CRCW040230K0FKED" 0402 3563.5,2261.38 r270 top value=30.0k
R66 "CRCW040230K0FKED" 0402 3513.5,2261.38 r270 top value=30.0k
R67 "CRCW040211K8FKED" 0402 1500,345 r180 bottom value=11.8k
R68 "HCS2512FT1L00" FP-HCS2512FT1L00_2512-MFG 3575,1820 r180 top value=1m
R69 "ERJ-3RQFR47V" 0603 3205.01,1900.56 r270 top value=0.47
R71 "ERJ-2GE0R00X" 0402 3450,1965 r180 top value=0
T1 "CB35-36-CY" CB35-36-CY 365,1893.82 r0 top
T2 "CB35-36-CY" CB35-36-CY 370,2410 r0 top
T3 "CB35-36-CY" CB35-36-CY 370.92,1279.2 r0 top
T4 "CB35-36-CY" CB35-36-CY 370,770 r0 top
T5 "CB35-36-CY" CB35-36-CY 4165,1745 r180 top
T6 "CB35-36-CY" CB35-36-CY 4166.83,1212.28 r180 top
TP1 "5000" Keystone5000 1150.58,3005 r270 top
TP2 "5004" Keystone5004 1370,3055 r270 top
TP3 "5001" Keystone5001 910,280 r0 top
TP4 "5003" Keystone5003 1325,540 r270 top
TP5 "5000" Keystone5000 1090,420 r270 top
TP6 "5004" Keystone5004 1135,195 r0 top
TP7 "5001" Keystone5001 500,390 r0 top
TP8 "5000" Keystone5000 810,1975 r90 top
TP9 "5001" Keystone5001 1040,2740 r180 top
TP10 "5000" Keystone5000 817.44,1206.59 r90 top
TP11 "5001" Keystone5001 500,2800 r180 top
U1 "LM25148QRGYRQ1" RGY0024E-MFG 1512.56,2817.17 r180 bottom
U2 "LM25148QRGYRQ1" RGY0024E-MFG 1555.87,345 r180 top
U3 "LM74912QRGEQ1" RGE0024T-MFG 3598.5,2100 r180 top

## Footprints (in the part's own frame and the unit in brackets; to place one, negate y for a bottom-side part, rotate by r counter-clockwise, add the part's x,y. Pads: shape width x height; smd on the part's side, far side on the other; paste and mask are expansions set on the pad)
0402 [mm] "0402 from SM-752 data"
  rect 0.8x0.6 smd: 1(-0.6,0) 2(0.6,0)
  silkscreen extent -1.22,-0.52 1.22,0.52, body extent -0.55,-0.3 0.55,0.3, height 0.6
0603 [mm] "0603 from SM-752 data"
  rect 1x0.95 smd: 1(-0.8,0) 2(0.8,0)
  silkscreen extent -1.52,-0.69 1.52,0.69, body extent -0.87,-0.47 0.87,0.47, height 1
0805_HV [mil] "0805 with 30mil clearance between pads"
  rect 50x63 smd: 1(-40,0) 2(40,0)
  silkscreen extent -74,-40 74,40, body extent -43,-29 43,29, height 57
1206 [mm] "1206 from SM-752 data"
  rect 1.3x1.85 smd: 1(-1.45,0) 2(1.45,0)
  silkscreen extent -2.4,-1.21 2.4,1.21, body extent -1.7,-0.9 1.7,0.9, height 1.35
1206_180 [mm] "1206_180"
  rect 1.1x1.6 smd: 1(-1.7,0) 2(1.7,0)
  silkscreen extent -0.9,-1 0.9,1, body extent -1.75,-0.95 1.75,0.95, height 1.8
1210_280 [mm] "SMD, 2-Leads, Body 3.6x2.8mm, Height 2.8mm"
  rect 1.1x2.2 smd: 1(-1.65,0) 2(1.65,0)
  silkscreen extent -0.84,-1.4 0.84,1.4, body extent -1.8,-1.4 1.8,1.4, height 2.8
7343-31 [mm] "Medium Density based on Kemet T495 dimensions"
  rect 2.55x2.45 smd: 1(-3.025,0) 2(3.025,0)
  silkscreen extent -4.56,-2.3 3.8,2.3, body extent -3.8,-2.3 3.8,2.3, height 3.1
CB35-36-CY [mil] "Terminal 50A Lug"
  rect 550x380 hole 188 copper offset -45,0 paste-190: 1(0,0)
  body extent -960,-189 230,191, height 614
FP-BUK9J0R9-40H_SOT1023-MFG [mm]
  rrect14% 0.7x1.15 smd paste-1000 mask+0: 1(-1.905,-3.137) 2(-0.635,-3.137) 3(0.635,-3.137) 4(1.905,-3.137)
  round 3.78 smd paste-1000 mask+0: 5(0,0.845)
  Top Layer region: -2.35,3.087 2.35,3.087 2.35,1.588 2.1,1.588 2.1,-1.512 -2.1,-1.512 -2.1,1.587 -2.35,1.587 -2.35,3.087
  silkscreen extent -2.65,-4.49 2.65,-1.89, body extent -2.9,-3.81 2.9,3.19, height 0.25
FP-CSSH0805FTL500_0805-MFG [mm]
  rrect7% 1.35x1.8 smd paste+0 mask+0: 1(-0.825,0) 2(0.825,0)
  silkscreen extent -1.15,-1.3 1.15,1.3, body extent -1.6,-1 1.6,1, height 0.25
FP-GCM32EC71H106KA03L_1210-MFG [mm]
  rrect9% 1.1x2.05 smd paste+0 mask+0: 1(-1.65,0) 2(1.65,0)
  silkscreen extent -0.72,-1.35 0.72,1.35, body extent -2.3,-1.45 2.3,1.45, height 0.25
FP-HCS2512FT1L00_2512-MFG [mm]
  rrect6% 1.8x3.4 smd paste+0 mask+0: 1(-2.8,0) 2(2.8,0)
  silkscreen extent -1.53,-1.73 1.53,1.73, body extent -3.8,-1.83 3.8,1.83, height 0.25
FP-IAUC120N04S6N009ATMA1_TDSON8-MFG [mm]
  rrect7% 3.14x1.5 smd paste-1000 mask-1000: 1-2-3(-0.635,-3.02)
  rrect17% 0.6x1.5 smd paste-1000 mask+0: 4(1.905,-3.02)
  rrect2% 4.41x4.9 smd paste-1000 mask-1000: 5-6-7-8(0,1.325)
  silkscreen extent -2.63,-4.45 2.63,2.79, body extent -2.96,-3.87 2.96,3.88, height 0.25
FP-WSL10203L000FEA_1020-MFG [mm]
  rrect8% 1.25x5.65 smd paste+0 mask+0: 1(-1.125,0) 2(1.125,0)
  silkscreen extent -0.13,-2.6 0.13,2.6, body extent -1.85,-2.93 1.85,2.93, height 0.25
FP-XGL1060-332MEC_SMT2_10MM0_11MM3-MFG [mm]
  rrect4% 2.38x8.5 smd paste+0 mask+0: 1(-3.325,0) 2(3.325,0)
  silkscreen extent -5.93,-5.9 5.25,5.9, body extent -5.35,-6 5.35,6, height 0.25
FP-XGL6060-472MEC_SMT2_6MM51_6MM71-MFG [mm]
  rrect7% 1.43x5.5 smd paste+0 mask+0: 1(-2.02,0) 2(2.02,0)
  silkscreen extent -3.95,-3.45 3.35,3.45, body extent -3.45,-3.55 3.45,3.55, height 0.25
IHLP-3232DZ [mil] "VISHAY"
  rrect5% 95x210 smd: 1(-142.5,0) 2(142.5,0)
  silkscreen extent -165,-165 165,165, body extent -169,-161 169,161, height 154
Keystone5000 [mil] "For Keystone 500x miniature loop terminals"
  round 80 hole 40: 1(0,0)
  silkscreen extent -52,-52 52,52, body extent -49,-49 49,49, height 182
Keystone5001 [mil] "For Keystone 500x miniature loop terminals"
  round 80 hole 40: 1(0,0)
  silkscreen extent -52,-52 52,52, body extent -49,-49 49,49, height 182
Keystone5003 [mil] "For Keystone 500x miniature loop terminals"
  round 80 hole 40: 1(0,0)
  silkscreen extent -52,-52 52,52, body extent -49,-49 49,49, height 182
Keystone5004 [mil] "For Keystone 500x miniature loop terminals"
  round 80 hole 40: 1(0,0)
  silkscreen extent -52,-52 52,52, body extent -49,-49 49,49, height 182
Mill-Max_800-10-004-10-001000 [mm] "Mill-Max"
  rect 1.5x1.5 hole 0.85: 1(-3.81,0)
  round 1.5 hole 0.85: 2(-1.27,0) 3(1.27,0) 4(3.81,0)
  silkscreen extent -5.08,-1.27 5.08,1.78, body extent -5.08,-1.27 5.08,1.27, height 8.13
Net-Tie_10milWide_30milLong#1 [mil] "10mil net tie, no solder mask opening, no solder paste"
  rect 30x10 on Mid2 paste-5 mask-5: 1(-15,0) 2(15,0)
Net-Tie_10milWide_30milLong#2 [mil] "10mil net tie, no solder mask opening, no solder paste"
  rect 30x10 smd paste-5 mask-5: 1(-15,0) 2(15,0)
RGE0024T-MFG [mm]
  rrect40% 0.6x0.25 smd paste+0 mask+0: 1(-1.9,1.25) 2(-1.9,0.75) 3(-1.9,0.25) 4(-1.9,-0.25) 5(-1.9,-0.75) 6(-1.9,-1.25) 13(1.9,-1.25) 14(1.9,-0.75) 15(1.9,-0.25) 16(1.9,0.25) 17(1.9,0.75) 18(1.9,1.25)
  rrect40% 0.25x0.6 smd paste+0 mask+0: 7(-1.25,-1.9) 8(-0.75,-1.9) 9(-0.25,-1.9) 10(0.25,-1.9) 11(0.75,-1.9) 12(1.25,-1.9) 19(1.25,1.9) 20(0.75,1.9) 21(0.25,1.9) 22(-0.25,1.9) 23(-0.75,1.9) 24(-1.25,1.9)
  rrect5% 2.1x2.1 smd paste-1000 mask+0: 25(0,0)
  silkscreen extent -2.88,-2.05 2.05,2.05, body extent -2.3,-2.3 2.3,2.3, height 0.25
RGY0024E-MFG [mm]
  rrect40% 0.25x0.6 smd paste+0 mask+0: 1(-0.75,2.65) 12(-0.75,-2.65) 13(0.75,-2.65) 24(0.75,2.65)
  rrect40% 0.6x0.25 smd paste+0 mask+0: 2(-1.65,2.25) 3(-1.65,1.75) 4(-1.65,1.25) 5(-1.65,0.75) 6(-1.65,0.25) 7(-1.65,-0.25) 8(-1.65,-0.75) 9(-1.65,-1.25) 10(-1.65,-1.75) 11(-1.65,-2.25) 14(1.65,-2.25) 15(1.65,-1.75) 16(1.65,-1.25) 17(1.65,-0.75) 18(1.65,-0.25) 19(1.65,0.25) 20(1.65,0.75) 21(1.65,1.25) 22(1.65,1.75) 23(1.65,2.25)
  rrect5% 2.1x4.1 smd paste-1000 mask+0: 25(0,0)
  silkscreen extent -1.8,-2.8 1.8,3.65, body extent -1.75,-2.75 1.75,2.75, height 1
RM1206 [mil] "1206"
  rect 36x67 smd: 1(-60,0) 2(60,0)
  silkscreen extent -95,-50 95,50, body extent -67,-34 67,34, height 33
SAMTEC_HMTSW-102-07-G-S-240 [mm] "Header, 2.54mm, 2x1, TH"
  rect 1.55x1.55 hole 1.02: 1(-1.27,0)
  round 1.55 hole 1.02: 2(1.27,0)
  silkscreen extent -3.01,-1.24 2.54,1.27, body extent -2.54,-1.27 2.54,1.27, height 8.64
Samtec_HTSW-103-07-G-S [mm] "Samtec 100mil, 1x3, 230 mil above insulator"
  rrect6% 1.65x1.65 hole 1.016: 1(-2.54,0)
  round 1.65 hole 1.016: 2(0,0) 3(2.54,0)
  silkscreen extent -4.57,-1.27 3.81,1.27, body extent -3.81,-1.27 3.81,1.27, height 8.38
SM_RADIAL_G [mm] "10 x 10.2mm:  Panasonic G"
  rect 4.1x2 smd: 1(-4.35,0) 2(4.35,0)
  silkscreen extent -5.35,-5.35 5.35,5.35, body extent -5.25,-5.25 5.25,5.25, height 10.5
SMAF [mm] "SMD, 2-Leads, Body 3.8x2.5mm"
  rect 1.24x1.89 smd: 1(-2.04,0) 2(2.04,0)
  silkscreen extent -3.4,-1.3 2.8,1.3, body extent -2.35,-1.25 2.35,1.25, height 1
SMB-Bi [mil] "Molded Diode, 2-Leads, Body 5.4x3.6mm, IPC Medium Density, based on OnSemi component dimensions"
  rect 85x107.99 smd: 1(-87.01,0) 2(87.01,0)
  silkscreen extent -125,-79 125,79, body extent -104,-73 104,73, height 89

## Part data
C1 C73: library part CMP-0860442-1, "CAP, AL, 330 µF, 50 V, +/- 20%, 0.12 ohm, AEC-Q200 Grade 2, SMD", Cap_Case=10x10.2mm, Manufacturer=Panasonic, Tolerance_%=20%, Value1="0.12 ohm", Value2=50V, ValueDisplayed=330µF
C2 C3 C4 C5 C6 C7 C8 C28 C29 C30 C31 C32 C33 C34 C54 C56 C101: library part CMP-0092251-1, "Ceramic Capacitor for Automotive 10uF ±10% 50VDC X7S 1210 Embossed T/R", Manufacturer=Murata, Operating Temperature Range="-55°C to +125°C", TempCo=22%, Temperature Characteristic=X7S, Tolerance_%=10%, ValueDisplayed=10uF
C9 C51 C52 C53 C99: library part CMP-0078224-1, "CAP, CERM, 0.01 µF, 50 V,+/- 10%, X8R, AEC-Q200 Grade 0, 0402", Cap_Case=0402, Manufacturer=TDK, Supplier Part Number 1=445-12303-1-ND, TempCo=X8R, Tolerance_%=10%, Value2=50V, ValueDisplayed=0.01µF
C10 C55 C78 C79 C80 C81 C82 C83 C84 C85 C86 C87 C88 C89 C90 C91 C92 C93 C94 C95 C96 C97 C98: library part CMP-0079911-1, "CAP, CERM, 0.1 µF, 50 V,+/- 10%, X8R, AEC-Q200 Grade 0, 0603", Cap_Case=0603, Manufacturer=TDK, Supplier Part Number 1=445-173697-1-ND, TempCo=X8R, Tolerance_%=10%, Value2=50V, ValueDisplayed=0.1µF
C11: library part CMP-0009162-2, "CAP, CERM, 4.7 uF, 50 V, +/- 10%, X7R, AEC-Q200 Grade 1, 1210", Cap_Case=1210_280, Manufacturer=TDK, Supplier Part Number 1=445-6999-1-ND, TempCo=X7R, Tolerance_%=10%, Value1="0.003166 ohm", Value2=50V, ValueDisplayed=4.7uF
C12: library part CMP-0008814-2, "CAP, CERM, 2.2 uF, 50 V, +/- 10%, X7R, AEC-Q200 Grade 1, 1206", Cap_Case=1206, Manufacturer=MuRata, Supplier Part Number 1=490-4796-1-ND, TempCo=X7R, Tolerance_%=10%, Value1=Unknown, Value2=50V, ValueDisplayed=2.2uF
C13: library part CMP-0006354-2, "CAP, CERM, 1000 pF, 50 V, +/- 10%, X7R, AEC-Q200 Grade 1, 0402", Cap_Case=0402, Manufacturer=MuRata, Supplier Part Number 1=490-4761-1-ND, TempCo=X7R, Tolerance_%=10%, Value1=Unknown, Value2=50V, ValueDisplayed=1000pF
C14 C18 C22 C25 C35 C39 C43 C45 C59 C60 C61 C62 C63 C64: library part CMP-0080610-1, "CAP, CERM, 0.1 µF, 25 V,+/- 10%, X7R, AEC-Q200 Grade 1, 0402", Cap_Case=0402, Manufacturer=TDK, Supplier Part Number 1=445-6902-1-ND, TempCo=X7R, Tolerance_%=10%, Value2=25V, ValueDisplayed=0.1µF
C15 C37: library part CMP-0006356-2, "CAP, CERM, 0.1 uF, 50 V, +/- 10%, X7R, AEC-Q200 Grade 1, 0402", Cap_Case=0402, Manufacturer=MuRata, Supplier Part Number 1=490-10672-1-ND, TempCo=X7R, Tolerance_%=10%, Value1=Unknown, Value2=50V, ValueDisplayed=DNP
C16 C17 C36: library part CMP-0084284-1, "CAP, CERM, 2.2 µF, 10 V,+/- 10%, X7R, AEC-Q200 Grade 1, 0603", Cap_Case=0603, Manufacturer=MuRata, TempCo=X7R, Tolerance_%=10%, Value2=10V, ValueDisplayed=2.2µF
C19 C20 C21 C40 C41 C42 C57 C58 C67 C68 C71 C72: library part CMP-0008811-3, "CAP, CERM, 22 uF, 10 V, +/- 10%, X7R, AEC-Q200 Grade 1, 1206", Cap_Case=1206, Manufacturer=MuRata, TempCo=X7R, Tolerance_%=10%, Value1=Unknown, Value2=10V, ValueDisplayed=22uF
C23 C26 C44 C47: library part CMP-0006327-2, "CAP, CERM, 0.015 uF, 50 V, +/- 10%, X7R, AEC-Q200 Grade 1, 0402", Cap_Case=0402, Manufacturer=TDK, Supplier Part Number 1=445-6894-1-ND, TempCo=X7R, Tolerance_%=10%, Value1="0.2162 ohm", Value2=50V, ValueDisplayed=0.015uF
C24: library part CMP-0006310-2, "CAP, CERM, 150 pF, 50 V, +/- 5%, C0G/NP0, AEC-Q200 Grade 1, 0402", Cap_Case=0402, Manufacturer=TDK, Supplier Part Number 1=445-5598-1-ND, TempCo=C0G/NP0, Tolerance_%=5%, Value1=Unknown, Value2=50V, ValueDisplayed=DNP
C27 C38 C65 C66 C69 C70: library part CMP-0012661-3, "CAP, Tantalum Polymer, 220 uF, 10 V, +/- 20%, 0.025 ohm, AEC-Q200 Grade 1, 7343-31 SMD", Cap_Case=7.3x4.3x3.1mm, Manufacturer=Kemet, Supplier Part Number 1=399-12102-1-ND, Tolerance_%=20%, Value1="0.025 ohm", Value2=10V, ValueDisplayed=220uF
C46: library part CMP-0006310-2, "CAP, CERM, 150 pF, 50 V, +/- 5%, C0G/NP0, AEC-Q200 Grade 1, 0402", Cap_Case=0402, Manufacturer=TDK, Supplier Part Number 1=445-5598-1-ND, TempCo=C0G/NP0, Tolerance_%=5%, Value1=Unknown, Value2=50V, ValueDisplayed=150pF
C48 C49 C50: library part CMP-0084548-1, "CAP, CERM, 0.1 µF, 50 V,+/- 10%, X7R, AEC-Q200 Grade 1, 0402", Cap_Case=0402, Manufacturer=TDK, TempCo=X7R, Tolerance_%=10%, Value2=50V, ValueDisplayed=0.1µF
C74 C75 C76 C77: library part CMP-0008361-2, "CAP, CERM, 0.01 uF, 100 V, +/- 10%, X7R, 0805", Cap_Case=0805, Manufacturer=MuRata, Supplier Part Number 1=490-1652-1-ND, TempCo=X7R, Tolerance_%=10%, Value1=Unknown, Value2=100V, ValueDisplayed=0.01uF
D1 D2: library part CMP-0028855-2, "Diode, Schottky, 40 V, 3 A, AEC-Q101, SMAF", Manufacturer="Fairchild Semiconductor", Value1=3A, Value2=0.5V
D3: library part CMP-0005564-3, "Diode, TVS, Bi, 33 V, SMB", Manufacturer="Diodes Inc.", Value1=600W
J1 J2 J5 J6: library part CMP-0075500-1, "Header, 100mil, 2x1, Gold, TH", Manufacturer=Samtec, Supplier Part Number 1=HMTSW-102-07-G-S-240-ND
J3: library part CMP-0055087-1, "Header, 100mil, 4x1, TH", Manufacturer=Mill-Max, Supplier Part Number 1=ED7204-ND
J4: library part CMP-0075484-1, "Header, 100mil, 3x1, Gold, TH", Manufacturer=Samtec, Supplier Part Number 1=HTSW-103-07-G-S-ND
L1: library part CMP-0063436-2, "Inductor, Shielded, Powdered Iron, 470 nH, 27 A, 0.00255 ohm, SMD", Manufacturer=Vishay-Dale, PartNumber=IHLP3232DZERR47M01, Supplier Part Number 1=541-1380-1-ND, Value1="0.00262 ohm", Value2=25A, ValueDisplayed=470nH
L2 L4: library part CMP-0092349-1, "Shielded Power Inductors 1.8uH, AEC Qualified SMD", Manufacturer=Coilcraft, Operating Temperature Range=to, Part Number=XGL6060-472MEC, Self Resonant Frequency=19MHz, Test Frequency=1MHz, Tolerance_%=20%
L3 L5 L6: library part CMP-0097455-1, "Shielded Power Inductors 3.3uH 22A 5.7mOhm", Manufacturer=Coilcraft, Operating Temperature Range=to, Part Number=XGL1060-332MEC, Self Resonant Frequency=21MHz, Test Frequency=1MHz, Tolerance_%=20%
NT1 NT2 NT3 NT4: library part CMP-0078142-6, "Single point connection between nets.", Manufacturer=N/A
Q1 Q2 Q3 Q4: library part CMP-0086959-1, "Trans Mosfet N-ch 40V 120A 8-PIN Pg-tdson T/R", Manufacturer=Infineon, PartNumber=IAUC120N04S6N009ATMA1
Q5 Q6: library part CMP-0086636-1, "N-channel 40 V, 0.9 mΩ logic level MOSFET in LFPAK56E", Manufacturer=Nexperia, PartNumber=BUK9J0R9-40H
R1: library part CMP-0022003-4, "RES, 10.0, 1%, 0.1 W, AEC-Q200 Grade 0, 0603", Manufacturer=Vishay-Dale, Power_W=100mW, Supplier Part Number 1=541-10.0HCT-ND, TempCo="100 ppm/C", Tolerance_%=1%, Value2=0.1W, Value_Code=10R0, ValueDisplayed=10.0
R2: library part CMP-0026790-1, "RES, 1.00 k, 0.1%, 0.063 W, AEC-Q200 Grade 0, 0402", Manufacturer=Panasonic, Power_W=63mW, Supplier Part Number 1=P1KCNCT-ND, TempCo="15 ppm/C", Tolerance_%=0.1%, Value2=0.063W, Value_Code=1k00, ValueDisplayed=1.00k
R3 R19 R48: library part CMP-0026702-1, "RES, 49.9 k, 1%, 0.1 W, AEC-Q200 Grade 0, 0402", Manufacturer=Panasonic, Power_W=100mW, Supplier Part Number 1=P49.9KLCT-ND, TempCo="100 ppm/C", Tolerance_%=1%, Value2=0.1W, Value_Code=49k9, ValueDisplayed=49.9k
R4 R36: library part CMP-0022306-4, "RES, 2.21, 1%, 0.1 W, AEC-Q200 Grade 0, 0603", Manufacturer=Vishay-Dale, Power_W=100mW, Supplier Part Number 1=541-2.21HHCT-ND, TempCo="100 ppm/C", Tolerance_%=1%, Value2=0.1W, Value_Code=2R21, ValueDisplayed=2.21
R5 R33 R64: library part CMP-0025950-3, "RES, 100 k, 1%, 0.063 W, AEC-Q200 Grade 0, 0402", Manufacturer=Vishay-Dale, Power_W=63mW, Supplier Part Number 1=541-100KLCT-ND, TempCo="100 ppm/C", Tolerance_%=1%, Value2=0.063W, Value_Code=100k
R6 R37: library part CMP-0097669-1, "3 mOhms ±1% 2W Chip Resistor Wide 2010 (5025 Metric), 1020 Anti-Sulfur, Automotive AEC-Q200, Current Sense, Moisture Resistant, Pulse Withstanding Metal Element", Digikey Part Number=541-10044-1-ND, Manufacturer=Vishay, Mouser Part Number=71-WSL10203L000FEA, Operating Temperature Range="-65°C to +170°C", Power_W=2W, TempCo=50ppm/°C, Tolerance_%=1%
R7: library part CMP-0026925-3, "RES, 3.0, 5%, 0.063 W, AEC-Q200 Grade 0, 0402", Manufacturer=Vishay-Dale, Power_W=63mW, Supplier Part Number 1=541-3.0JCT-ND, TempCo="200 ppm/C", Tolerance_%=5%, Value2=0.063W, Value_Code=3R00, ValueDisplayed=3.0
R8 R38: library part CMP-0025697-4, "RES, 0, 5%, 0.1 W, AEC-Q200 Grade 0, 0603", Manufacturer=Vishay-Dale, Power_W=100mW, Supplier Part Number 1=541-0.0GCT-ND, TempCo="200 ppm/C", Tolerance_%=5%, Value2=0.1W, Value_Code=0000, ValueDisplayed=DNP
R9 R41: library part CMP-0025697-4, "RES, 0, 5%, 0.1 W, AEC-Q200 Grade 0, 0603", Manufacturer=Vishay-Dale, Power_W=100mW, Supplier Part Number 1=541-0.0GCT-ND, TempCo="200 ppm/C", Tolerance_%=5%, Value2=0.1W, Value_Code=0000, ValueDisplayed=0
R10 R22 R25 R35 R40 R43 R52 R54 R71: library part CMP-0026992-3, "RES, 0, 5%, 0.1 W, AEC-Q200 Grade 0, 0402", Manufacturer=Panasonic, Power_W=100mW, Supplier Part Number 1=P0.0JCT-ND, TempCo="600 ppm/C", Tolerance_%=5%, Value2=0.1W, Value_Code=0000, ValueDisplayed=0
R11 R15 R17 R21 R42 R44 R45 R49: library part CMP-0026992-3, "RES, 0, 5%, 0.1 W, AEC-Q200 Grade 0, 0402", Manufacturer=Panasonic, Power_W=100mW, Supplier Part Number 1=P0.0JCT-ND, TempCo="600 ppm/C", Tolerance_%=5%, Value2=0.1W, Value_Code=0000, ValueDisplayed=DNP
R12 R23 R51 R58: library part CMP-0026703-1, "RES, 49.9, 1%, 0.1 W, AEC-Q200 Grade 0, 0402", Manufacturer=Panasonic, Power_W=100mW, Supplier Part Number 1=P49.9LCT-ND, TempCo="100 ppm/C", Tolerance_%=1%, Value2=0.1W, Value_Code=49R9, ValueDisplayed=49.9
R13: library part CMP-0026196-2, "RES, 24.9 k, 1%, 0.063 W, AEC-Q200 Grade 0, 0402", Manufacturer=Vishay-Dale, Power_W=63mW, Supplier Part Number 1=541-24.9KLCT-ND, TempCo="100 ppm/C", Tolerance_%=1%, Value2=0.063W, Value_Code=24k9, ValueDisplayed=24.9k
R14: library part CMP-0026883-3, "RES, 24 k, 5%, 0.063 W, AEC-Q200 Grade 0, 0402", Manufacturer=Vishay-Dale, Power_W=63mW, Supplier Part Number 1=541-24KJCT-ND, TempCo="200 ppm/C", Tolerance_%=5%, Value2=0.063W, Value_Code=24k0, ValueDisplayed=24k
R16: library part CMP-0026395-2, "RES, 47.5 k, 1%, 0.063 W, AEC-Q200 Grade 0, 0402", Manufacturer=Vishay-Dale, Power_W=63mW, Supplier Part Number 1=541-47.5KLCT-ND, TempCo="100 ppm/C", Tolerance_%=1%, Value2=0.063W, Value_Code=47k5, ValueDisplayed=47.5k
R18 R67: library part CMP-0025978-3, "RES, 11.8 k, 1%, 0.063 W, AEC-Q200 Grade 0, 0402", Manufacturer=Vishay-Dale, Power_W=63mW, Supplier Part Number 1=541-11.8KLCT-ND, TempCo="100 ppm/C", Tolerance_%=1%, Value2=0.063W, Value_Code=11k8, ValueDisplayed=11.8k
R20: library part CMP-0026535-2, "RES, 71.5 k, 1%, 0.063 W, AEC-Q200 Grade 0, 0402", Manufacturer=Vishay-Dale, Power_W=63mW, Supplier Part Number 1=541-71.5KLCT-ND, TempCo="100 ppm/C", Tolerance_%=1%, Value2=0.063W, Value_Code=71k5, ValueDisplayed=71.5k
